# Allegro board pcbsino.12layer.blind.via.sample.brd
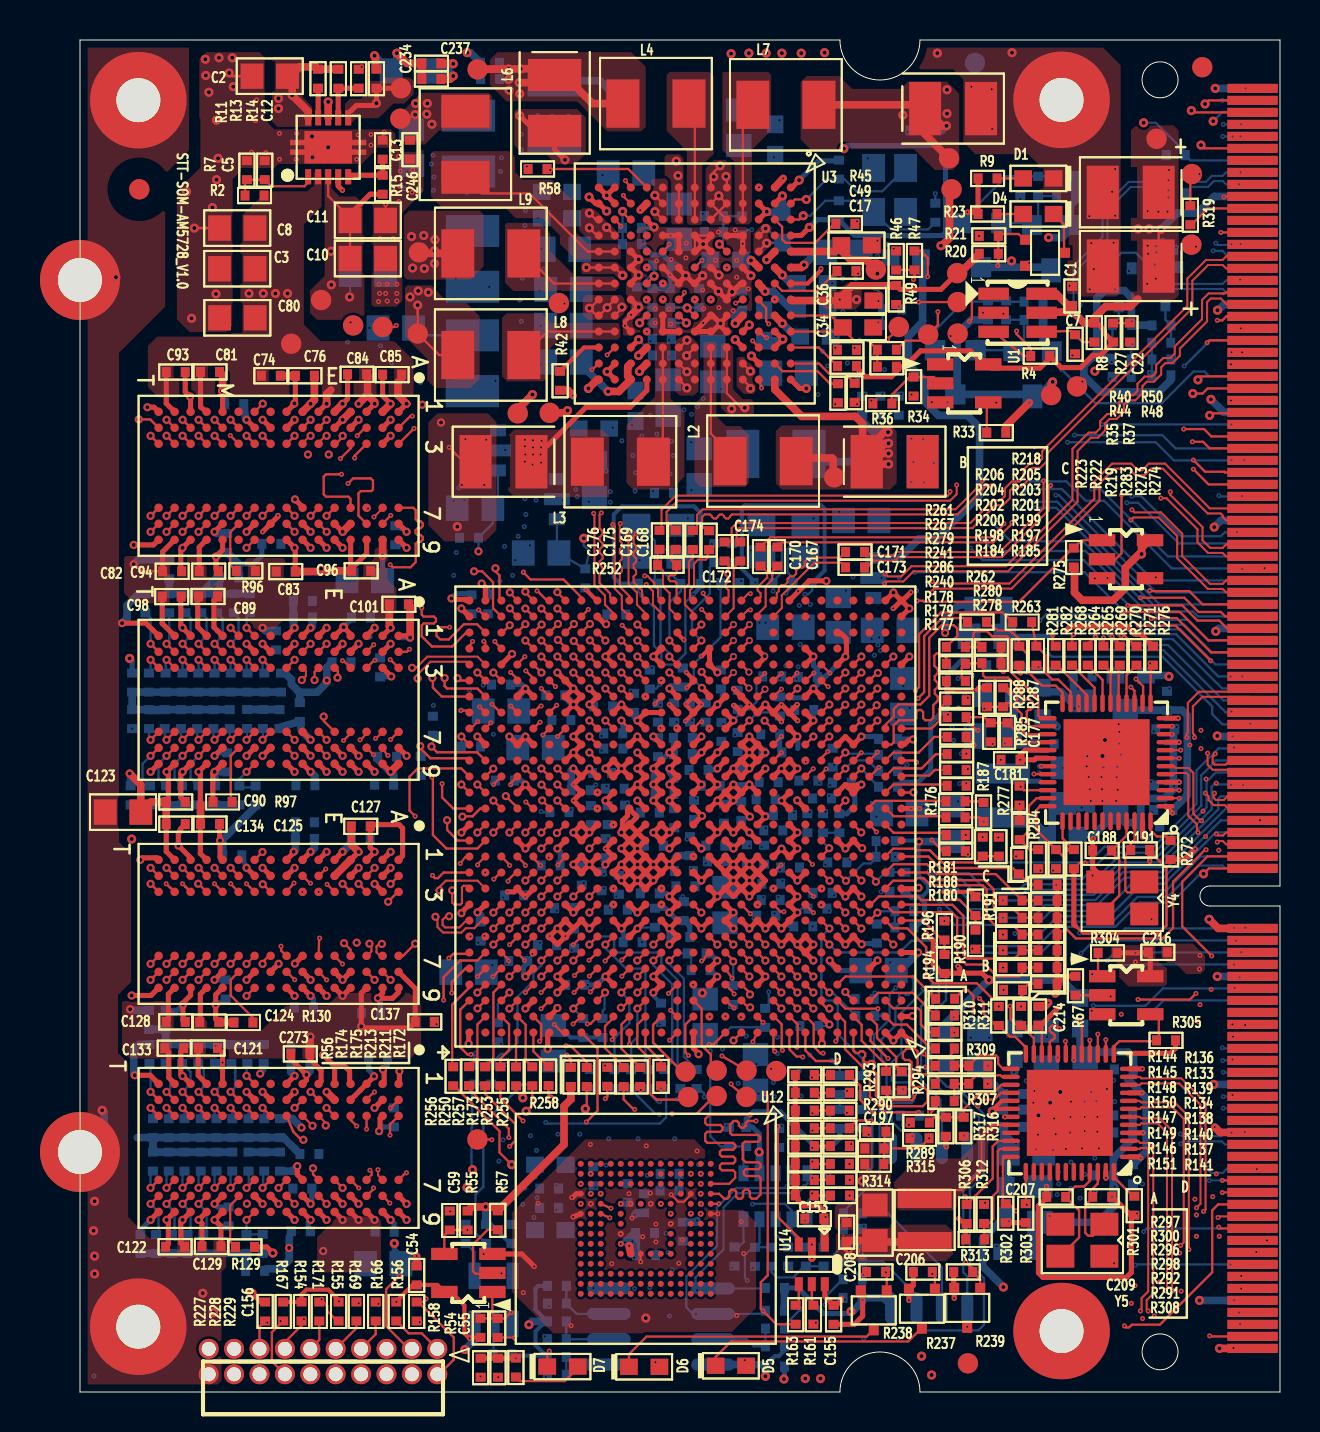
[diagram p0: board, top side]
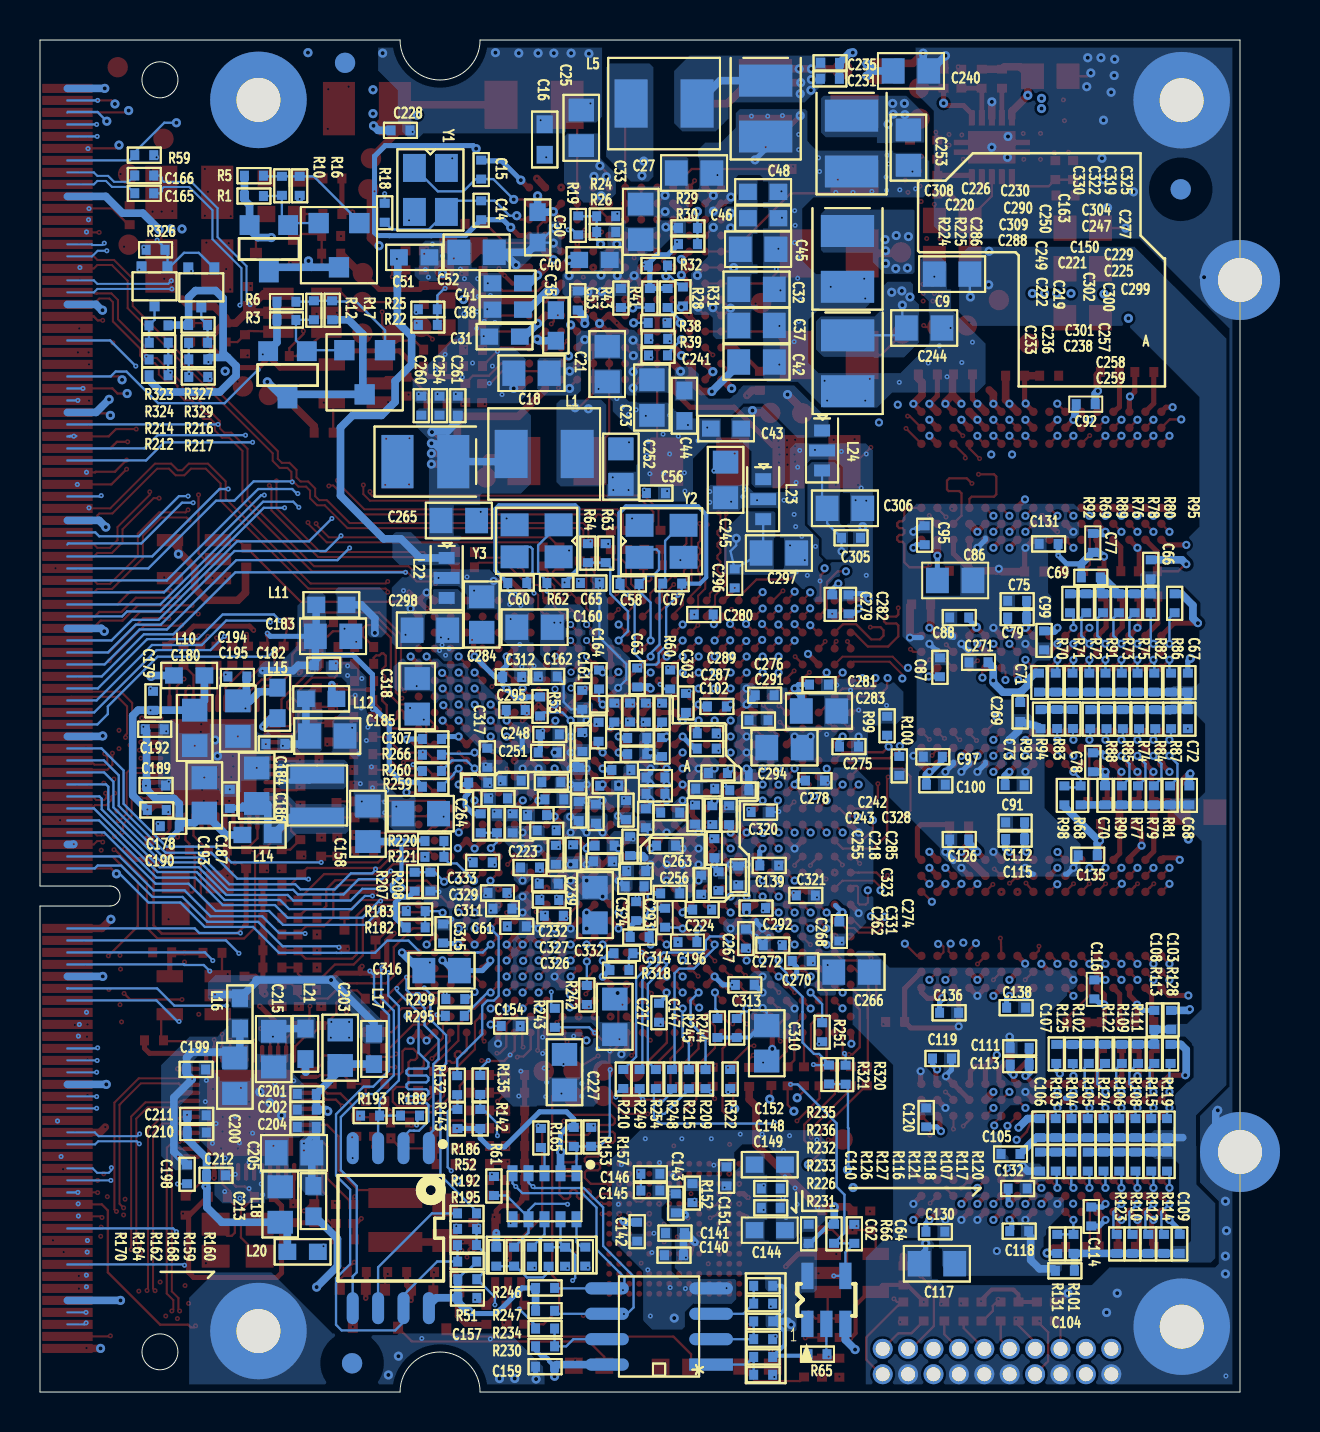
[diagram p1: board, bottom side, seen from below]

Outline 60 x 67.6 mm; copper layers: TOP, GND_L2, INT_L3, GND_L4, SIG_L5, PWR_L6, PWR_L7, SIG_L8, GND_L9, SIG_L10, GND_L11, BOTTOM. Coordinates in mm from the lower left corner of the outline.
Outline path: circle c54,2.01 r0.9 ; circle c54,65.61 r0.9 ; 0,67.6 38,67.6 arc(40,65.6) 42,67.6 60,67.6 60,25.3 56.5,25.3 arc(56,24.8) 56.5,24.3 60,24.3 60,0 42,0 arc(40,2) 38,0 0,0 0,67.6

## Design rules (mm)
net group DDR1_CLK: nets DDR1_CLK_N DDR1_CLK_P
net group EMMC_NAND_MMC2_DAT2: nets EMMC_NAND__MMC2_DAT2 EMMC_NAND_MMC2_DAT2
net group LDO_VRTC: nets N25853972 N32694377
net group R_QSPI_FLASH_QSPI1_SCLK: nets R__QSPI_FLASH_QSPI1_SCLK R_QSPI_FLASH_QSPI1_SCLK
net group RTC_CLKOUT_1V8: nets N29245750 RTC_CLKOUT_1V8
net group SATA1_RX0: nets SATA1_RX0_N SATA1_RX0_P
net group SATA1_TX0_N: nets SATA1_TX0_N SODIMM_SATA1_TX0_N
net group SATA1_TX0_P: nets SATA1_TX0_P SODIMM_SATA1_TX0_P
net group SODIMM_ETH0_MDI0: nets SODIMM_ETH0_MDI0_N SODIMM_ETH0_MDI0_P
net group SODIMM_ETH0_MDI2: nets SODIMM_ETH0_MDI2_N SODIMM_ETH0_MDI2_P
net group SODIMM_ETH0_MDI3: nets SODIMM_ETH0_MDI3_N SODIMM_ETH0_MDI3_P
net group SODIMM_ETH1_MDI0: nets SODIMM_ETH1_MDI0_N SODIMM_ETH1_MDI0_P
net group SODIMM_ETH1_MDI1: nets SODIMM_ETH1_MDI1_N SODIMM_ETH1_MDI1_P
net group SODIMM_ETH1_MDI3: nets SODIMM_ETH1_MDI3_N SODIMM_ETH1_MDI3_P
net group SODIMM_SATA1_RX0: nets SODIMM_SATA1_RX0_N SODIMM_SATA1_RX0_P
net group SODIMM_UART8_RXD: nets SODIMM__UART8_RXD SODIMM_UART8_RXD
net group SODIMM_USB1_D: nets SODIMM_USB1_D_N SODIMM_USB1_D_P
net group SODIMM_USB1_RX0: nets SODIMM_USB1_RX0_N SODIMM_USB1_RX0_P
net group SODIMM_USB1_TX0: nets SODIMM_USB1_TX0_N SODIMM_USB1_TX0_P
net group SODIMM_USB2_D: nets SODIMM_USB2_D_N SODIMM_USB2_D_P
net group USB1_TX0: nets USB1_TX0_N USB1_TX0_P
net group D1: nets DDR2_D15
net group EMAC[0]_RXC/PHYAD1: nets EMAC[0]_RXC/PHYAD1
net group EMAC[0]_RXCTL/PHYAD2: nets EMAC[0]_RXCTL/PHYAD2
net group EMAC[0]_RXD2/CFG_MODE1: nets R_EMAC[0]_RXD2
net group EMAC[0]_RXD3/CFG_MODE2: nets R_EMAC[0]_RXD3
net group EMAC[0]_TXC: nets EMAC[0]_TXC
net group EMAC[0]_TXCTL: nets EMAC[0]_TXCTL
net group EMAC[0]_TXD0: nets EMAC[0]_TXD0
net group EMAC[0]_TXD1: nets EMAC[0]_TXD1
net group EMAC[0]_TXD2: nets EMAC[0]_TXD2
net group EMAC[0]_TXD3: nets EMAC[0]_TXD3
net group EMAC[1]_RXCTL/PHYAD2: nets R_EMAC[1]_RXCTL
net group EMAC[1]_RXD1/CFG_MODE0: nets R_EMAC[1]_RXD1
net group EMAC[1]_TXC: nets EMAC[1]_TXC
net group EMAC[1]_TXCTL: nets EMAC[1]_TXCTL
net group EMAC[1]_TXD0: nets EMAC[1]_TXD0
net group EMAC[1]_TXD1: nets EMAC[1]_TXD1
net group EMAC[1]_TXD2: nets EMAC[1]_TXD2
net group EMAC[1]_TXD3: nets EMAC[1]_TXD3
net group HDMI: nets SODIMM_HDMI1_CLOCK_N SODIMM_HDMI1_CLOCK_P SODIMM_HDMI1_DATA0_N SODIMM_HDMI1_DATA0_P SODIMM_HDMI1_DATA1_N SODIMM_HDMI1_DATA1_P SODIMM_HDMI1_DATA2_N SODIMM_HDMI1_DATA2_P
net group LJCB_CLK_N: nets SODIMM_PCIE_REF_LJCB_CLK_N
net group LJCB_CLK_P: nets SODIMM_PCIE_REF_LJCB_CLK_P
net group PCIE_TX0_N: nets SODIMM_PCIE_TX0_N
net group PCIE_TX0_P: nets SODIMM_PCIE_TX0_P
net group PCIE_TX1_N: nets SODIMM_PCIE_TX1_N
net group PCIE_TX1_P: nets SODIMM_PCIE_TX1_P
net group RSTOUTN: nets R_QSPI_FLASH_QSPI1_D3
nets with their own width: min track width 0.102; nets GND
nets with their own width: min track width 0.254; nets LDO_VRTC

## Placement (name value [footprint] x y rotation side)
C1  0.1uF  [0402]  49.6 54.8 270 top
C2  10uF  [0805]  9.49 65.79 180 top
C3  10uF  [0805]  7.86 56.16 0 top
C4  47uF  [1210]  52.53 56.3 180 top
C5  .001uF  [0402]  9.23 61.09 90 top
C6  47uF  [1210]  52.53 59.98 180 top
C7  DNI  [0402]  49.75 52.39 270 top
C8  10uF  [0805]  7.86 58.2 0 top
C9  10uF  [0805]  14.39 55.89 0 bottom
C10  10uF  [0805]  14.39 56.67 0 top
C11  10uF  [0805]  14.39 58.58 0 top
C12  0.1uF  [0402]  14.82 65.66 90 top
C13  DNI  [0402]  15.13 62.12 90 top
C14  10pF  [0402]  37.94 59.09 270 bottom
C15  10pF  [0402]  37.94 61.12 90 bottom
C16  2.2uF  [0603]  34.76 62.62 90 bottom
C17  0.1uF  [0402]  38.32 56.05 180 top
C18  4.7uF  [0805]  35.42 50.94 0 bottom
C19  47uF  [1210]  40.73 46.52 0 top
C20  47uF  [1210]  40.73 46.52 0 bottom
C21  4.7uF  [0805]  31.64 51.4 270 bottom
C22  0.1uF  [0402]  52.49 52.97 270 top
C23  4.7uF  [0805]  29.4 49.72 270 bottom
C24  47uF  [1210]  21.18 46.51 180 top
C25  4.7uF  [0805]  32.94 63.21 90 bottom
C26  47uF  [1210]  23.73 64.46 270 top
C27  4.7uF  [0805]  27.3 60.95 180 bottom
C28  47uF  [1210]  23.71 64.17 270 bottom
C29  47uF  [1210]  19.42 62.42 270 bottom
C30  47uF  [1210]  43.65 64.17 0 top
C31  2.2uF  [0603]  36.77 52.77 180 bottom
C32  4.7uF  [0805]  24.17 55.13 180 bottom
C33  4.7uF  [0805]  29.96 58.51 270 bottom
C34  2.2uF  [0603]  38.9 53.23 0 top
C35  2.2uF  [0603]  34.21 53.33 90 bottom
C36  2.2uF  [0603]  38.9 54.57 180 top
C37  4.7uF  [0805]  24.17 53.33 180 bottom
C38  2.2uF  [0603]  36.62 54.12 0 bottom
C39  47uF  [1210]  19.62 51.44 270 bottom
C40  2.2uF  [0603]  32.28 56.6 0 bottom
C41  2.2uF  [0603]  36.62 55.44 180 bottom
C42  10uF  [0805]  24.17 51.5 180 bottom
C43  2.2uF  [0603]  25.7 48.17 180 bottom
C44  2.2uF  [0603]  27.78 49.31 90 bottom
C45  4.7uF  [0805]  24.1 57.14 180 bottom
C46  2.2uF  [0603]  23.84 58.69 0 bottom
C47  47uF  [1210]  19.62 56.66 270 bottom
C48  2.2uF  [0603]  23.84 60.01 0 bottom
C49  2.2uF  [0603]  38.83 57.34 180 top
C50  2.2uF  [0603]  35.12 58.23 270 bottom
C51  2.2uF  [0603]  41.29 56.73 0 bottom
C52  10uF  [0805]  38.17 56.99 0 bottom
C53  0.1uF  [0402]  33.11 54.57 90 bottom
C54  0.1uF  [0402]  16.83 5.83 90 top
C55  0.1uF  [0402]  20.88 3.2 270 top
C56  0.1uF  [0402]  29.2 44.95 180 bottom
C57  18pF  [0402]  28.39 40.42 180 bottom
C58  18pF  [0402]  30.52 40.4 0 bottom
C59  DNI  [0402]  18.49 8.58 90 top
C60  DNI  [0402]  36.14 40.45 0 bottom
C61  0.1uF  [0402]  36.16 23.28 0 bottom
C62  0.1uF  [0402]  21.57 7.91 90 bottom
C63  0.1uF  [0402]  30.14 35.73 90 bottom
C64  DNI  [0402]  19.28 7.91 90 bottom
C65  0.1uF  [0402]  32.5 40.45 0 bottom
C66  0.1uF  [0402]  4.46 41.14 90 bottom
C67  0.1uF  [0402]  2.61 35.47 90 bottom
C68  0.1uF  [0402]  2.53 29.83 90 bottom
C69  0.1uF  [0402]  7.46 40.73 0 bottom
C70  0.1uF  [0402]  6.75 29.83 90 bottom
C71  0.1uF  [0402]  10.05 35.47 90 bottom
C72  0.1uF  [0402]  2.61 33.64 270 bottom
C73  0.1uF  [0402]  9.97 33.64 270 bottom
C74  0.1uF  [0402]  9.54 50.81 0 top
C75  0.1uF  [0402]  11.14 39.56 180 bottom
C76  0.1uF  [0402]  11.24 50.81 0 top
C77  0.1uF  [0402]  7.36 42.46 270 bottom
C78  0.1uF  [0402]  7.36 31.48 270 bottom
C79  0.1uF  [0402]  11.14 38.72 0 bottom
C80  10uF  [0805]  7.87 53.71 180 top
C81  0.1uF  [0402]  6.5 51 180 top
C82  0.1uF  [0402]  4.61 41.03 180 top
C83  0.1uF  [0402]  10.29 41.02 0 top
C84  0.1uF  [0402]  13.85 50.88 0 top
C85  0.1uF  [0402]  15.61 50.87 0 top
C86  10uF  [0805]  14.24 40.58 0 bottom
C87  0.1uF  [0402]  15 36.23 90 bottom
C88  0.1uF  [0402]  14.04 38.72 0 bottom
C89  0.1uF  [0402]  6.4 39.78 180 top
C90  0.1uF  [0402]  4.79 29.5 180 top
C91  0.1uF  [0402]  11.27 30.34 180 bottom
C92  0.1uF  [0402]  7.71 49.39 180 bottom
C93  0.1uF  [0402]  4.79 51 0 top
C94  0.1uF  [0402]  6.44 41.04 0 top
C95  0.1uF  [0402]  15.77 42.84 270 bottom
C96  0.1uF  [0402]  14.06 41.06 0 top
C97  0.1uF  [0402]  15.36 31.76 180 bottom
C98  0.1uF  [0402]  4.58 39.77 0 top
C99  0.1uF  [0402]  9.8 37.58 90 bottom
C100  0.1uF  [0402]  15.21 30.37 0 bottom
C101  0.1uF  [0402]  15.94 39.38 180 top
C102  0.1uF  [0402]  26.66 32.93 180 bottom
C103  0.1uF  [0402]  3.45 18.61 90 bottom
C104  0.1uF  [0402]  8.75 6.06 0 bottom
C105  0.1uF  [0402]  11.47 11.9 0 bottom
C106  0.1uF  [0402]  10 13.2 90 bottom
C107  0.1uF  [0402]  9.19 16.9 270 bottom
C108  0.1uF  [0402]  4.28 18.61 90 bottom
C109  0.1uF  [0402]  3.01 7.4 90 bottom
C110  0.1uF  [0402]  10 11.52 270 bottom
C111  0.1uF  [0402]  11.02 17.21 180 bottom
C112  0.1uF  [0402]  11.24 28.49 180 bottom
C113  0.1uF  [0402]  11.02 16.37 0 bottom
C114  0.1uF  [0402]  7.43 8.78 270 bottom
C115  0.1uF  [0402]  11.24 27.65 0 bottom
C116  0.1uF  [0402]  7.28 20.13 270 bottom
C117  10uF  [0805]  15.16 6.41 0 bottom
C118  0.1uF  [0402]  11.04 8.04 180 bottom
C119  0.1uF  [0402]  14.9 16.68 180 bottom
C120  0.1uF  [0402]  15.69 13.73 90 bottom
C121  0.1uF  [0402]  6.4 17.2 180 top
C122  0.1uF  [0402]  4.75 7.26 180 top
C123  10uF  [0805]  2.15 28.99 180 top
C124  0.1uF  [0402]  6.46 18.49 180 top
C125  0.1uF  [0402]  6.5 28.4 180 top
C126  0.1uF  [0402]  14.04 27.62 0 bottom
C127  0.1uF  [0402]  14.04 28.28 0 top
C128  0.1uF  [0402]  4.79 18.5 180 top
C129  0.1uF  [0402]  6.57 7.28 0 top
C130  0.1uF  [0402]  15.23 8.01 0 bottom
C131  0.1uF  [0402]  9.57 42.41 180 bottom
C132  0.1uF  [0402]  11.12 10.17 0 bottom
C133  0.1uF  [0402]  4.71 17.19 0 top
C134  0.1uF  [0402]  4.79 28.39 0 top
C135  0.1uF  [0402]  7.61 26.84 180 bottom
C136  0.1uF  [0402]  14.55 18.96 0 bottom
C137  0.1uF  [0402]  17.24 18.5 0 top
C138  0.1uF  [0402]  11.19 19.22 0 bottom
C139  0.1uF  [0402]  23.54 26.33 0 bottom
C140  0.1uF  [0402]  28.3 6.84 180 bottom
C141  0.1uF  [0402]  28.25 7.94 180 bottom
C142  0.1uF  [0402]  30.14 8.01 90 bottom
C143  0.1uF  [0402]  28.21 9.44 270 bottom
C144  2.2uF  [0603]  23.51 8.09 180 bottom
C145  0.1uF  [0402]  29.48 10.07 180 bottom
C146  1uF  [0402]  29.48 10.91 0 bottom
C147  0.1uF  [0402]  29.05 18.96 90 bottom
C148  0.1uF  [0402]  23.46 10.17 0 bottom
C149  0.1uF  [0402]  23.46 9.21 0 bottom
C150  0.1uF  [0402]  30.93 31.1 0 bottom
C151  0.1uF  [0402]  25.67 10.78 270 bottom
C152  2.2uF  [0603]  23.51 11.37 180 bottom
C153  0.1uF  [0402]  36.72 8.67 180 top
C154  0.1uF  [0402]  36.47 18.3 180 bottom
C155  0.1uF  [0402]  37.68 3.86 270 top
C156  0.1uF  [0402]  9.26 4.03 90 top
C157  0.1uF  [0402]  38.63 4.7 0 bottom
C158  10uF  [0805]  43.6 28.41 90 bottom
C159  0.1uF  [0402]  34.75 1.27 0 bottom
C160  10uF  [0805]  35.27 38.24 0 bottom
C161  0.1uF  [0402]  32.88 34.61 90 bottom
C162  0.1uF  [0402]  34.61 35.78 0 bottom
C163  0.1uF  [0402]  32.07 33.01 90 bottom
C164  0.1uF  [0402]  32.05 35.62 90 bottom
C165  0.1uF  [0402]  54.79 59.94 0 bottom
C166  0.1uF  [0402]  54.79 60.82 0 bottom
C167  0.1uF  [0402]  34.87 41.77 270 top
C168  0.1uF  [0402]  31.46 42.59 90 top
C169  0.1uF  [0402]  30.64 42.6 90 top
C170  0.1uF  [0402]  34.03 41.77 270 top
C171  0.1uF  [0402]  38.75 42 180 top
C172  0.1uF  [0402]  32.22 42.02 90 top
C173  0.1uF  [0402]  38.75 41.24 180 top
C174  0.1uF  [0402]  33.01 42.02 90 top
C175  0.1uF  [0402]  29.79 42.61 270 top
C176  0.1uF  [0402]  28.97 42.61 270 top
C177  DNI  [0402]  46.37 32.98 270 top
C178  0.1uF  [0402]  54.16 29.1 0 bottom
C179  0.1uF  [0402]  54.35 34.56 270 bottom
C180  10uF  [0805]  52.27 33.2 270 bottom
C181  0.1uF  [0402]  46.52 31.61 180 top
C182  0.1uF  [0402]  45.81 36.34 180 bottom
C183  10uF  [0805]  45.35 37.78 180 bottom
C184  0.1uF  [0402]  48.23 32.4 0 bottom
C185  10uF  [0805]  45.64 32.8 180 bottom
C186  10uF  [0805]  49.17 30.32 90 bottom
C187  0.1uF  [0402]  50.51 29.65 90 bottom
C188  27pF  [0402]  51.11 27.08 180 top
C189  0.1uF  [0402]  54.2 30.33 180 bottom
C190  0.1uF  [0402]  53.51 28.28 0 bottom
C191  27pF  [0402]  53.01 27.1 0 top
C192  0.1uF  [0402]  54.26 33.14 180 bottom
C193  10uF  [0805]  51.78 29.83 90 bottom
C194  0.1uF  [0402]  50.13 35.78 0 bottom
C195  10uF  [0805]  50.11 33.67 270 bottom
C196  0.1uF  [0402]  27.63 22.49 0 bottom
C197  DNI  [0402]  39.72 12.18 180 top
C198  0.1uF  [0402]  52.65 10.88 270 bottom
C199  0.1uF  [0402]  52.19 16.13 180 bottom
C200  10uF  [0805]  50.26 15.81 270 bottom
C201  0.1uF  [0402]  46.66 14.9 0 bottom
C202  0.1uF  [0402]  46.66 14.12 0 bottom
C203  10uF  [0805]  44.99 17.22 90 bottom
C204  0.1uF  [0402]  46.66 13.25 0 bottom
C205  10uF  [0805]  47.3 11.96 0 bottom
C206  10uF  [0805]  39.75 8.47 90 top
C207  27pF  [0402]  48.81 9.75 180 top
C208  0.1uF  [0402]  38.33 8 90 top
C209  27pF  [0402]  51.11 9.76 0 top
C210  0.1uF  [0402]  52.16 12.98 180 bottom
C211  0.1uF  [0402]  52.16 13.83 180 bottom
C212  0.1uF  [0402]  51.2 10.83 180 bottom
C213  10uF  [0805]  47.99 9.38 90 bottom
C214  0.1uF  [0402]  47.92 18.8 90 top
C215  10uF  [0805]  48.31 17.15 270 bottom
C216  0.1uF  [0402]  53.89 21.98 0 top
C217  10uF  [0805]  31.26 18.76 270 bottom
C218  0.1uF  [0402]  26.38 28.84 270 bottom
C219  0.1uF  [0402]  32.2 28.92 90 bottom
C220  0.1uF  [0402]  37.1 29.68 0 bottom
C221  0.1uF  [0402]  31.54 30.32 180 bottom
C222  0.1uF  [0402]  33.06 29.05 90 bottom
C223  0.1uF  [0402]  35.5 26.23 180 bottom
C224  0.1uF  [0402]  26.89 24.12 180 bottom
C225  0.1uF  [0402]  29.23 29.91 0 bottom
C226  0.1uF  [0402]  36.42 30.57 0 bottom
C227  10uF  [0805]  33.77 15.99 270 bottom
C228  0.1uF  [0402]  41.98 63.08 180 bottom
C229  0.1uF  [0402]  29.23 30.72 0 bottom
C230  0.1uF  [0402]  34.43 30.49 180 bottom
C231  0.1uF  [0402]  20.51 65.66 180 bottom
C232  0.1uF  [0402]  34.56 25.41 0 bottom
C233  0.1uF  [0402]  34.21 26.86 90 bottom
C234  0.1uF  [0402]  17.57 65.65 180 top
C235  0.1uF  [0402]  20.5 66.46 180 bottom
C236  0.1uF  [0402]  33.34 26.89 90 bottom
C237  0.1uF  [0402]  17.57 66.43 180 top
C238  0.1uF  [0402]  31.84 26.53 180 bottom
C239  10uF  [0805]  32.25 24.35 270 bottom
C240  10uF  [0805]  16.45 66.05 180 bottom
C241  0.1uF  [0402]  29.1 51.83 0 bottom
C242  0.1uF  [0402]  26.1 30.95 180 bottom
C243  0.1uF  [0402]  26.74 30.16 180 bottom
C244  10uF  [0805]  15.79 53.2 180 bottom
C245  10uF  [0805]  25.72 45.61 270 bottom
C246  0.1uF  [0402]  16.5 62.12 270 top
C247  0.1uF  [0402]  30.14 31.89 180 bottom
C248  0.1uF  [0402]  34.51 32.88 0 bottom
C249  0.1uF  [0402]  33.06 30.75 270 bottom
C250  0.1uF  [0402]  32.88 32.5 90 bottom
C251  0.1uF  [0402]  34.62 31.98 0 bottom
C252  10uF  [0805]  30.95 46.27 270 bottom
C253  10uF  [0805]  16.58 62.22 270 bottom
C254  0.1uF  [0402]  40.02 49.31 90 bottom
C255  0.1uF  [0402]  27.25 28.87 90 bottom
C256  0.1uF  [0402]  28.49 24.93 0 bottom
C257  0.1uF  [0402]  30.5 27.29 90 bottom
C258  0.1uF  [0402]  30.19 26.05 0 bottom
C259  0.1uF  [0402]  30.27 25.29 0 bottom
C260  0.1uF  [0402]  40.94 49.31 90 bottom
C261  0.1uF  [0402]  39.11 49.31 90 bottom
C262  0.1uF  [0402]  26.94 25.36 270 bottom
C263  0.1uF  [0402]  28.69 27.32 0 bottom
C264  10uF  [0805]  40.96 28.92 0 bottom
C265  10uF  [0805]  39.06 43.57 180 bottom
C266  10uF  [0805]  19.42 20.99 0 bottom
C267  0.1uF  [0402]  24.71 22.67 270 bottom
C268  0.1uF  [0402]  20.03 23.03 270 bottom
C269  0.1uF  [0402]  10.99 34 90 bottom
C270  0.1uF  [0402]  21.91 21.55 180 bottom
C271  0.1uF  [0402]  13.07 36.49 180 bottom
C272  0.1uF  [0402]  23.36 22.34 180 bottom
C273  0.1uF  [0402]  11.02 16.9 180 top
C274  0.1uF  [0402]  25.09 25.82 270 bottom
C275  0.1uF  [0402]  19.55 32.27 180 bottom
C276  0.1uF  [0402]  23.77 34.84 180 bottom
C277  0.1uF  [0402]  28.9 32.25 270 bottom
C278  0.1uF  [0402]  21.25 30.57 180 bottom
C279  0.1uF  [0402]  20.39 39.38 270 bottom
C280  0.1uF  [0402]  26.81 38.88 0 bottom
C281  0.1uF  [0402]  21.05 35.37 180 bottom
C282  0.1uF  [0402]  19.58 39.38 90 bottom
C283  10uF  [0805]  21.05 34.05 180 bottom
C284  10uF  [0805]  37.91 38.88 90 bottom
C285  0.1uF  [0402]  25.54 28.84 90 bottom
C286  0.1uF  [0402]  36.36 28.44 90 bottom
C287  0.1uF  [0402]  26.66 32.17 180 bottom
C288  0.1uF  [0402]  34.66 28.08 180 bottom
C289  0.1uF  [0402]  26.15 34.28 180 bottom
C290  0.1uF  [0402]  34.28 29.63 180 bottom
C291  0.1uF  [0402]  24.07 33.59 180 bottom
C292  0.1uF  [0402]  24.2 24.19 180 bottom
C293  0.1uF  [0402]  28.74 23.71 90 bottom
C294  10uF  [0805]  22.78 32.22 180 bottom
C295  0.1uF  [0402]  36.21 34.1 180 bottom
C296  0.1uF  [0402]  25.26 40.68 270 bottom
C297  10uF  [0805]  23.05 41.95 180 bottom
C298  10uF  [0805]  40.5 38.09 0 bottom
C299  0.1uF  [0402]  28.49 28.97 0 bottom
C300  0.1uF  [0402]  29.71 28.69 90 bottom
C301  0.1uF  [0402]  31.77 27.32 180 bottom
C302  0.1uF  [0402]  30.7 29.1 90 bottom
C303  0.1uF  [0402]  27.7 34.46 90 bottom
C304  0.1uF  [0402]  30.14 32.7 180 bottom
C305  0.1uF  [0402]  19.45 42.71 180 bottom
C306  10uF  [0805]  19.75 44.18 180 bottom
C307  0.1uF  [0402]  40.4 32.65 0 bottom
C308  0.1uF  [0402]  38.09 30.47 180 bottom
C309  0.1uF  [0402]  35.15 28.84 0 bottom
C310  10uF  [0805]  23.66 17.44 270 bottom
C311  0.1uF  [0402]  36.87 24.17 0 bottom
C312  0.1uF  [0402]  36.39 35.75 180 bottom
C313  0.1uF  [0402]  24.76 20.36 0 bottom
C314  0.1uF  [0402]  30.01 22.75 0 bottom
C315  0.1uF  [0402]  39.84 22.92 90 bottom
C316  10uF  [0805]  39.92 21.07 0 bottom
C317  0.1uF  [0402]  37.63 31.71 270 bottom
C318  10uF  [0805]  41.14 34.79 270 bottom
C319  1uF  [0402]  29.71 33.97 270 bottom
C320  1uF  [0402]  23.97 28.99 180 bottom
C321  1uF  [0402]  21.71 24.83 0 bottom
C322  1uF  [0402]  30.5 33.97 90 bottom
C323  1uF  [0402]  26.28 27.19 90 bottom
C324  1uF  [0402]  30.19 24.04 270 bottom
C325  1uF  [0402]  28.9 33.97 270 bottom
C326  1uF  [0402]  34.31 23.81 180 bottom
C327  1uF  [0402]  34.54 24.6 180 bottom
C328  1uF  [0402]  25.04 30.09 180 bottom
C329  1uF  [0402]  37.13 24.96 180 bottom
C330  1uF  [0402]  31.28 33.97 90 bottom
C331  1uF  [0402]  26.08 25.54 270 bottom
C332  1uF  [0402]  30.83 21.93 0 bottom
C333  1uF  [0402]  37.86 26.48 180 bottom
D1  LTST-C191KGKT  [LED_0603]  47.92 60.68 180 top
D2  TLVH431LIL3T  [SOT23-3L]  45.05 57.34 0 bottom
D3  TLVH431LIL3T  [SOT23-3L]  43.77 50.99 0 bottom
D4  LTST-C191KGKT  [LED_0603]  47.92 58.9 180 top
D5  LTST-C191KGKT  [LED_0603]  32.55 1.31 0 top
D6  LTST-C191KRKT  [LED_0603]  28.21 1.26 0 top
D7  LTST-C191TBKT  [LED_0603]  24.12 1.27 0 top
L1  1.0uH  [IND_IHLP1616AB]  34.79 46.9 0 bottom
L2  1.0uH  [IND_IHLP1616AB]  34.15 46.55 0 top
L3  1.0uH  [IND_IHLP1616AB]  27.02 46.51 180 top
L4  1.0uH  [IND_IHLP1616AB]  28.8 64.42 180 top
L5  1.0uH  [IND_IHLP1616AB]  28.8 64.42 180 bottom
L6  1.0uH  [IND_IHLP1616AB]  19.27 62.39 90 top
L7  1.0uH  [IND_IHLP1616AB]  35.29 64.36 0 top
L8  1.0uH  [IND_IHLP1616AB]  20.54 51.85 180 top
L9  1.0uH  [IND_IHLP1616AB]  20.54 56.93 180 top
L10  BLM18KG601SN1D  [0603]  52.54 35.83 0 bottom
L11  BLM18KG601SN1D  [0603]  45.43 39.36 180 bottom
L12  BLM18KG601SN1D  [0603]  45.94 34.66 180 bottom
L13  2.2uH_1A  [SRN3015]  46.14 29.83 180 bottom
L14  BLM18KG601SN1D  [0603]  49.12 27.85 180 bottom
L15  BLM18KG601SN1D  [0603]  48.12 34.46 270 bottom
L16  BLM18KG601SN1D  [0603]  50 18.94 90 bottom
L17  BLM18KG601SN1D  [0603]  43.3 17.16 90 bottom
L18  BLM18KG601SN1D  [0603]  46.33 9.54 270 bottom
L19  2.2uH_1A  [SRN3015]  42.23 8.6 0 top
L20  BLM18KG601SN1D  [0603]  46.87 7.01 180 bottom
L21  BLM18KG601SN1D  [0603]  46.72 17.41 270 bottom
L22  NFM21PC474R1C3D  [FILT-NFM21PC]  39.67 40.7 270 bottom
L23  NFM21PC474R1C3D  [FILT-NFM21PC]  23.84 44.64 270 bottom
L24  NFM21PC474R1C3D  [FILT-NFM21PC]  20.9 47.08 270 bottom
MH1  MOUNT_HOLE  [2P2_5P0_MM_PL]  49.08 64.6 0 top
MH2  MOUNT_HOLE  [2P2_5P0_MM_PL]  49.08 3.05 0 top
MH3  MOUNT_HOLE  [2P2_5P0_MM_PL]  2.91 3.27 0 top
MH4  MOUNT_HOLE  [2P2_5P0_MM_PL]  2.92 64.59 0 top
MH5  MOUNT_HOLE  [2P0_4P0_MM_PL]  0 55.6 0 top
MH6  MOUNT_HOLE  [2P0_4P0_MM_PL]  0 12 0 top
NOREF  -  [unnamed]  56.11 66.24 0 top
NOREF#2  -  [#2]  36.54 -92.04 0 top
NOREF#3  -  [unnamed]  2.96 60.13 0 top
NOREF#4  -  [#2]  -387 -278.1 0 top
NOREF#5  -  [unnamed]  44.4 1.43 0 top
NOREF#6  -  [#2]  -386.87 -278.02 0 top
NOREF#7  -  [unnamed]  2.96 60.13 180 bottom
NOREF#8  -  [unnamed]  44.4 1.44 180 bottom
NOREF#9  -  [unnamed]  44.75 66.46 180 bottom
P1  DNI  [PLLD1_27-20R]  12.15 1.52 180 top
Q1  MMBT2907A-7-F  [SOT23]  48.56 57.16 0 bottom
Q2  MMBT2907A-7-F  [SOT23]  47.63 50.86 0 bottom
Q3  BSS138W-7-F  [SOT323]  48.25 56.96 270 top
Q4  BSS138W-7-F  [SOT323]  42.1 4.16 180 top
Q5  BSS138W-7-F  [SOT323]  39.69 4.08 180 top
Q6  BSS138W-7-F  [SOT323]  44.36 4.21 180 top
Q7  BSS138W-7-F  [SOT323]  54.27 55.28 0 bottom
Q8  BSS138W-7-F  [SOT323]  51.93 55.23 0 bottom
R1  499  [0402]  49.3 59.8 0 bottom
R2  10K,1%  [0402]  8.73 59.82 180 top
R3  499  [0402]  47.68 53.6 0 bottom
R4  10K  [0402]  48.01 51.8 0 top
R5  DNI  [0402]  49.3 60.82 0 bottom
R6  DNI  [0402]  47.68 54.52 0 bottom
R7  10K,1%  [0402]  8.34 61.09 270 top
R8  47K  [0402]  50.72 52.97 90 top
R9  1K  [0402]  45.38 60.68 0 top
R10  10K  [0402]  47.91 60.31 90 bottom
R11  100K  [0402]  11.9 65.66 270 top
R12  10K  [0402]  46.31 54.09 90 bottom
R13  10K  [0402]  12.92 65.66 90 top
R14  DNI  [0402]  13.93 65.66 90 top
R15  0  [0402]  15.13 60.36 90 top
R16  24.3K  [0402]  47.02 60.31 90 bottom
R17  24.3K  [0402]  45.39 54.09 90 bottom
R18  DNI  [0402]  42.77 58.96 270 bottom
R19  DNI  [0402]  33.09 58.33 90 bottom
R20  10K  [0402]  45.44 56.91 180 top
R21  DNI  [0402]  45.44 57.8 180 top
R22  2K  [0402]  40.61 53.35 180 bottom
R23  1K  [0402]  45.38 58.9 0 top
R24  10K  [0402]  31.69 58.79 0 bottom
R25  1.74K  [0402]  40.61 54.13 180 bottom
R26  DNI  [0402]  31.69 58 0 bottom
R27  10K  [0402]  51.66 52.97 90 top
R28  10K  [0402]  28.62 54.7 270 bottom
R29  10K  [0402]  27.6 58.2 0 bottom
R30  DNI  [0402]  27.6 57.39 0 bottom
R31  DNI  [0402]  27.86 54.78 270 bottom
R32  10K  [0402]  29.1 56.32 0 bottom
R33  10K  [0402]  45.81 47.97 180 top
R34  10K  [0402]  41.68 50.27 270 top
R35  10K  [0402]  37.9 49.94 90 top
R36  0  [0402]  40.12 49.43 180 top
R37  DNI  [0402]  38.73 49.96 90 top
R38  10K  [0402]  29.12 53.46 0 bottom
R39  DNI  [0402]  29.09 52.66 180 bottom
R40  10K  [0402]  38.35 52.11 180 top
R41  10K  [0402]  29.51 54.7 270 bottom
R42  10K  [0402]  24 50.56 90 top
R43  DNI  [0402]  30.95 54.7 90 bottom
R44  0  [0402]  38.35 51.3 180 top
R45  0  [0402]  38.27 58.41 180 top
R46  DNI  [0402]  40.81 56.58 90 top
R47  1K  [0402]  41.72 56.58 90 top
R48  0  [0402]  40.34 51.27 0 top
R49  3.9K  [0402]  40.81 54.85 270 top
R50  DNI  [0402]  40.34 52.12 180 top
R51  DNI  [0402]  38.64 5.64 0 bottom
R52  DNI  [0402]  38.65 8.16 0 bottom
R53  DNI  [0402]  34.99 34.28 270 bottom
R54  10K  [0402]  20.02 3.2 90 top
R55  10K  [0402]  19.38 8.58 90 top
R56  10K  [0402]  24.54 15.75 270 top
R57  4.7K  [0402]  20.89 8.58 90 top
R58  10K  [0402]  22.88 61.15 180 top
R59  10K  [0402]  54.79 61.84 180 bottom
R60  10K  [0402]  28.49 35.62 90 bottom
R61  DNI  [0402]  37.3 10.3 90 bottom
R62  10K  [0402]  34.18 40.45 180 bottom
R63  DNI  [0402]  31.72 41.94 270 bottom
R64  10K  [0402]  32.61 41.94 90 bottom
R65  10K  [0402]  21.12 1.89 180 bottom
R66  DNI  [0402]  20.3 7.91 90 bottom
R67  DNI  [0402]  49.77 20.31 270 top
R68  47  [0402]  7.97 29.83 90 bottom
R69  47  [0402]  7.69 39.43 270 bottom
R70  47  [0402]  9.21 35.47 90 bottom
R71  47  [0402]  8.37 35.47 90 bottom
R72  47  [0402]  7.54 35.47 90 bottom
R73  47  [0402]  5.91 35.47 90 bottom
R74  47  [0402]  5.05 33.64 270 bottom
R75  47  [0402]  5.12 35.47 90 bottom
R76  47  [0402]  6.06 39.43 270 bottom
R77  47  [0402]  5.1 29.83 90 bottom
R78  47  [0402]  5.27 39.43 270 bottom
R79  47  [0402]  4.31 29.83 90 bottom
R80  47  [0402]  4.46 39.43 270 bottom
R81  47  [0402]  3.5 29.83 90 bottom
R82  47  [0402]  4.28 35.47 90 bottom
R83  47  [0402]  7.48 33.64 270 bottom
R84  47  [0402]  4.23 33.64 270 bottom
R85  47  [0402]  5.86 33.64 270 bottom
R86  47  [0402]  3.45 35.47 90 bottom
R87  47  [0402]  3.45 33.64 270 bottom
R88  47  [0402]  6.67 33.64 270 bottom
R89  47  [0402]  6.85 39.43 270 bottom
R90  47  [0402]  5.91 29.83 90 bottom
R91  47  [0402]  6.72 35.47 90 bottom
R92  47  [0402]  8.5 39.43 270 bottom
R93  49.9  [0402]  9.14 33.65 270 bottom
R94  49.9  [0402]  8.35 33.65 270 bottom
R95  10K  [0402]  3.27 39.43 90 bottom
R96  240,1%  [0402]  8.29 41.05 0 top
R97  240,1%  [0402]  7.13 29.5 180 top
R98  10K  [0402]  8.78 29.83 270 bottom
R99  1K  [0402]  17.64 33.31 270 bottom
R100  1K  [0402]  17.04 31.31 90 bottom
R101  47  [0402]  8.32 7.4 90 bottom
R102  47  [0402]  7.56 16.9 270 bottom
R103  47  [0402]  9.21 13.2 90 bottom
R104  47  [0402]  8.42 13.2 90 bottom
R105  47  [0402]  7.61 13.2 90 bottom
R106  47  [0402]  6.04 13.2 90 bottom
R107  47  [0402]  5.22 11.52 270 bottom
R108  47  [0402]  5.22 13.2 90 bottom
R109  47  [0402]  5.91 16.9 270 bottom
R110  47  [0402]  5.38 7.4 90 bottom
R111  47  [0402]  5.1 16.9 270 bottom
R112  47  [0402]  4.59 7.4 90 bottom
R113  47  [0402]  4.28 16.9 270 bottom
R114  47  [0402]  3.8 7.4 90 bottom
R115  47  [0402]  4.44 13.2 90 bottom
R116  47  [0402]  7.61 11.52 270 bottom
R117  47  [0402]  4.44 11.52 270 bottom
R118  47  [0402]  6.04 11.52 270 bottom
R119  47  [0402]  3.65 13.2 90 bottom
R120  47  [0402]  3.65 11.52 270 bottom
R121  47  [0402]  6.82 11.52 270 bottom
R122  47  [0402]  6.75 16.9 270 bottom
R123  47  [0402]  6.16 7.4 90 bottom
R124  47  [0402]  6.82 13.2 90 bottom
R125  47  [0402]  8.37 16.9 270 bottom
R126  49.9  [0402]  9.21 11.52 270 bottom
R127  49.9  [0402]  8.42 11.52 270 bottom
R128  10K  [0402]  3.47 16.9 90 bottom
R129  240,1%  [0402]  8.25 7.25 0 top
R130  240,1%  [0402]  8.17 18.48 180 top
R131  10K  [0402]  9.14 7.4 270 bottom
R132  22  [0402]  39.14 15.34 270 bottom
R133  22  [0402]  38 14.96 180 top
R134  22  [0402]  37.99 13.19 180 top
R135  22  [0402]  37.99 15.35 270 bottom
R136  22  [0402]  38 15.85 180 top
R137  22  [0402]  38 10.6 180 top
R138  22  [0402]  37.99 12.3 180 top
R139  22  [0402]  37.99 14.07 180 top
R140  22  [0402]  37.99 11.4 180 top
R141  22  [0402]  38 9.82 180 top
R142  DNI  [0402]  37.98 13.65 90 bottom
R143  10K  [0402]  39.13 13.65 90 bottom
R144  47K  [0402]  36.24 15.85 0 top
R145  47K  [0402]  36.24 14.96 0 top
R146  47K  [0402]  36.24 10.6 0 top
R147  47K  [0402]  36.24 12.3 0 top
R148  47K  [0402]  36.24 14.08 0 top
R149  47K  [0402]  36.24 11.41 0 top
R150  47K  [0402]  36.24 13.19 0 top
R151  47K  [0402]  36.24 9.83 0 top
R152  DNI  [0402]  27.38 9.94 270 bottom
R153  DNI  [0402]  33.31 12.75 90 bottom
R154  4.7K  [0402]  11.08 4.03 270 top
R155  4.7K  [0402]  12.93 4.03 270 top
R156  4.7K  [0402]  15.81 4.03 270 top
R157  10K  [0402]  32.44 12.75 90 bottom
R158  4.7K  [0402]  16.83 4.03 270 top
R159  DNI  [0402]  33.75 6.76 270 bottom
R160  0  [0402]  32.73 6.77 90 bottom
R161  10K  [0402]  36.67 3.86 90 top
R162  0  [0402]  35.4 6.77 90 bottom
R163  22  [0402]  35.78 3.86 90 top
R164  1M  [0402]  36.29 6.77 90 bottom
R165  22  [0402]  34.96 12.7 90 bottom
R166  22  [0402]  14.78 4.03 270 top
R167  4.7K  [0402]  10.16 4.03 270 top
R168  0  [0402]  34.57 6.76 270 bottom
R169  22  [0402]  13.82 4.03 270 top
R170  DNI  [0402]  37.18 6.77 270 bottom
R171  22  [0402]  11.96 4.03 270 top
R172  DNI  [0402]  29.05 15.78 270 top
R173  22  [0402]  21.02 15.78 270 top
R174  22  [0402]  25.34 15.75 270 top
R175  22  [0402]  26.37 15.76 270 top
R176  0  [0402]  43.78 29.53 0 top
R177  22  [0402]  43.83 30.32 0 top
R178  22  [0402]  43.83 31.89 0 top
R179  22  [0402]  43.83 31.1 0 top
R180  22  [0402]  43.79 27.04 0 top
R181  22  [0402]  43.78 28.73 0 top
R182  10K  [0402]  41.22 23.23 180 bottom
R183  DNI  [0402]  41.22 24.04 0 bottom
R184  10K  [0402]  46.65 20.1 180 top
R185  DNI  [0402]  48.38 20.41 180 top
R186  10  [0402]  38.65 8.93 0 bottom
R187  10  [0402]  45.17 29 90 top
R188  22  [0402]  43.79 27.85 0 top
R189  DNI  [0402]  41.5 13.82 180 bottom
R190  DNI  [0402]  44.77 22.62 90 top
R191  10K  [0402]  44.77 24.3 90 top
R192  DNI  [0402]  38.65 7.35 180 bottom
R193  10K  [0402]  43.5 13.82 0 bottom
R194  DNI  [0402]  43.22 21.4 90 top
R195  10K  [0402]  38.64 6.52 180 bottom
R196  10K  [0402]  43.22 23.08 90 top
R197  DNI  [0402]  48.38 21.22 180 top
R198  10K  [0402]  46.63 21.22 180 top
R199  DNI  [0402]  48.38 22.09 180 top
R200  10K  [0402]  46.63 22.09 180 top
R201  DNI  [0402]  48.38 22.87 180 top
R202  10K  [0402]  46.63 22.87 180 top
R203  10K  [0402]  48.38 23.71 180 top
R204  DNI  [0402]  46.63 23.71 180 top
R205  DNI  [0402]  48.38 24.57 180 top
R206  10K  [0402]  46.63 24.57 180 top
R207  DNI  [0402]  41.27 25.51 90 bottom
R208  10K  [0402]  40.48 25.51 270 bottom
R209  22  [0402]  26.72 15.64 270 bottom
R210  22  [0402]  30.83 15.65 270 bottom
R211  22  [0402]  28.01 15.75 270 top
R212  DNI  [0402]  54.07 50.84 180 bottom
R213  22  [0402]  27.18 15.74 270 top
R214  DNI  [0402]  54.07 51.63 0 bottom
R215  22  [0402]  27.56 15.64 270 bottom
R216  DNI  [0402]  52.09 51.63 0 bottom
R217  DNI  [0402]  52.09 50.76 180 bottom
R218  DNI  [0402]  48.38 25.36 180 top
R219  10K  [0402]  46.94 26.38 90 top
R220  10K  [0402]  40.28 27.55 180 bottom
R221  DNI  [0402]  40.28 26.76 0 bottom
R222  10K  [0402]  45.94 27.27 270 top
R223  DNI  [0402]  45.13 27.27 90 top
R224  10K  [0402]  37.96 28.44 270 bottom
R225  DNI  [0402]  37.15 28.44 90 bottom
R226  DNI  [0402]  23.84 1.75 180 bottom
R227  1K  [0402]  20.03 1.21 270 top
R228  1K  [0402]  20.9 1.21 270 top
R229  1K  [0402]  21.79 1.22 270 top
R230  DNI  [0402]  34.75 2.28 0 bottom
R231  DNI  [0402]  23.84 0.86 180 bottom
R232  DNI  [0402]  23.84 3.53 180 bottom
R233  DNI  [0402]  23.84 2.64 180 bottom
R234  DNI  [0402]  34.75 3.17 180 bottom
R235  DNI  [0402]  23.84 5.31 180 bottom
R236  0  [0402]  23.84 4.42 180 bottom
R237  10K  [0402]  42.14 6 0 top
R238  10K  [0402]  39.8 6 0 top
R239  10K  [0402]  44.16 6 0 top
R240  22  [0402]  43.83 32.75 0 top
R241  22  [0402]  43.83 34.59 0 top
R242  22  [0402]  32.66 19.85 270 bottom
R243  22  [0402]  34.26 18.71 270 bottom
R244  2.2K  [0402]  25.16 18.2 90 bottom
R245  2.2K  [0402]  26.13 18.2 90 bottom
R246  2.2K  [0402]  34.75 5.2 0 bottom
R247  2.2K  [0402]  34.75 4.06 0 bottom
R248  22  [0402]  28.4 15.65 270 bottom
R249  22  [0402]  30.02 15.65 270 bottom
R250  22  [0402]  19.45 15.79 270 top
R251  22  [0402]  20.89 17.99 270 bottom
R252  100  [0402]  29.35 41.34 180 top
R253  22  [0402]  21.8 15.78 270 top
R254  22  [0402]  29.21 15.65 270 bottom
R255  22  [0402]  22.61 15.79 270 top
R256  22  [0402]  18.66 15.79 270 top
R257  22  [0402]  20.25 15.78 270 top
R258  22  [0402]  23.43 15.8 270 top
R259  1.5K  [0402]  40.4 30.26 0 bottom
R260  22  [0402]  40.4 31.05 0 bottom
R261  22  [0402]  43.79 37.25 0 top
R262  22  [0402]  44.85 38.49 0 top
R263  22  [0402]  47.11 38.49 0 top
R264  22  [0402]  49.6 36.82 270 top
R265  22  [0402]  50.39 36.82 270 top
R266  22  [0402]  40.4 31.86 0 bottom
R267  22  [0402]  43.79 36.41 0 top
R268  22  [0402]  48.79 36.82 270 top
R269  22  [0402]  51.17 36.82 270 top
R270  22  [0402]  51.99 36.82 270 top
R271  22  [0402]  52.82 36.82 270 top
R272  2.49K 1%  [0402]  54.53 27.1 90 top
R273  4.7K  [0402]  48.8 26.64 90 top
R274  4.7K  [0402]  49.69 26.64 90 top
R275  4.7K  [0402]  49.69 41.72 90 top
R276  4.7K  [0402]  53.65 36.82 270 top
R277  4.7K  [0402]  46.97 29.82 90 top
R278  4.7K  [0402]  45.57 36.44 180 top
R279  DNI  [0402]  43.79 35.55 180 top
R280  4.7K  [0402]  45.57 37.25 180 top
R281  4.7K  [0402]  46.97 36.81 90 top
R282  4.7K  [0402]  47.82 36.82 90 top
R283  DNI  [0402]  47.91 26.64 90 top
R284  4.7K  [0402]  46.99 28.09 90 top
R285  4.7K  [0402]  45.53 32.98 90 top
R286  DNI  [0402]  43.83 33.74 180 top
R287  4.7K  [0402]  46.16 34.74 270 top
R288  DNI  [0402]  45.35 34.74 90 top
R289  22  [0402]  41.99 13.48 0 top
R290  22  [0402]  39.82 13.02 0 top
R291  22  [0402]  43.24 15.41 0 top
R292  22  [0402]  43.23 16.31 0 top
R293  22  [0402]  40.3 15.56 270 top
R294  22  [0402]  41.09 15.56 270 top
R295  22  [0402]  39.26 18.81 0 bottom
R296  22  [0402]  43.25 17.99 0 top
R297  22  [0402]  43.26 19.66 0 top
R298  22  [0402]  43.24 17.18 0 top
R299  22  [0402]  39.23 19.65 0 bottom
R300  22  [0402]  43.24 18.82 0 top
R301  2.49K 1%  [0402]  52.71 9.32 90 top
R302  4.7K  [0402]  46.29 8.94 90 top
R303  4.7K  [0402]  47.28 8.94 90 top
R304  4.7K  [0402]  51.38 21.96 180 top
R305  4.7K  [0402]  54.3 17.58 180 top
R306  4.7K  [0402]  44.33 8.9 90 top
R307  4.7K  [0402]  44.91 15.41 180 top
R308  DNI  [0402]  43.24 14.54 180 top
R309  4.7K  [0402]  44.92 16.31 180 top
R310  4.7K  [0402]  45.94 18.8 270 top
R311  4.7K  [0402]  47.06 18.8 270 top
R312  4.7K  [0402]  45.2 8.9 270 top
R313  DNI  [0402]  44.76 7.63 180 top
R314  DNI  [0402]  39.72 11.39 0 top
R315  4.7K  [0402]  41.98 12.69 180 top
R316  4.7K  [0402]  44.19 13.26 90 top
R317  DNI  [0402]  43.3 13.26 270 top
R318  DNI  [0402]  31.03 21.1 0 bottom
R319  0  [0402]  55.52 58.84 90 top
R320  DNI  [0402]  19.72 15.87 270 bottom
R321  0  [0402]  20.55 15.87 270 bottom
R322  22  [0402]  25.49 15.65 270 bottom
R323  1K  [0402]  54.07 53.33 180 bottom
R324  10K  [0402]  54.06 52.46 180 bottom
R326  100K  [0402]  54.22 57.11 0 bottom
R327  1K  [0402]  52.09 53.35 0 bottom
R329  10K  [0402]  52.09 52.46 0 bottom
TP1  TP1mm  [TP_SMD1MMCIRCLE]  53.83 62.66 0 top
TP2  TP1mm  [TP_SMD1MMCIRCLE]  12.06 54.6 90 top
TP3  TP1mm  [TP_SMD1MMCIRCLE]  16.04 65.19 90 top
TP4  TP1mm  [TP_SMD1MMCIRCLE]  13.66 53.33 0 top
TP5  TP1mm  [TP_SMD1MMCIRCLE]  37.71 45.73 0 top
TP6  TP1mm  [TP_SMD1MMCIRCLE]  40.94 53.25 0 top
TP7  TP1mm  [TP_SMD1MMCIRCLE]  43.88 54.5 0 top
TP8  TP1mm  [TP_SMD1MMCIRCLE]  10.56 52.41 0 top
TP9  TP1mm  [TP_SMD1MMCIRCLE]  23.94 54.45 0 top
TP10  TP1mm  [TP_SMD1MMCIRCLE]  15.13 53.25 0 top
TP11  TP1mm  [TP_SMD1MMCIRCLE]  19.88 66.13 0 top
TP12  TP1mm  [TP_SMD1MMCIRCLE]  55.57 57.37 0 top
TP13  TP1mm  [TP_SMD1MMCIRCLE]  16.02 63.67 0 top
TP14  TP1mm  [TP_SMD1MMCIRCLE]  43.45 61.68 0 top
TP15  TP1mm  [TP_SMD1MMCIRCLE]  43.86 55.94 0 top
TP16  TP1mm  [TP_SMD1MMCIRCLE]  42.41 52.87 0 top
TP17  TP1mm  [TP_SMD1MMCIRCLE]  43.88 52.92 0 top
TP18  TP1mm  [TP_SMD1MMCIRCLE]  16.88 52.92 90 top
TP19  TP1mm  [TP_SMD1MMCIRCLE]  49.85 50.28 0 top
TP20  TP1mm  [TP_SMD1MMCIRCLE]  48.56 49.85 0 top
TP21  TP1mm  [TP_SMD1MMCIRCLE]  23.49 48.96 0 top
TP22  TP1mm  [TP_SMD1MMCIRCLE]  21.89 48.93 0 top
TP23  TP1mm  [TP_SMD1MMCIRCLE]  16.95 56.98 0 top
TP24  TP1mm  [TP_SMD1MMCIRCLE]  39.79 56.12 0 top
TP25  TP1mm  [TP_SMD1MMCIRCLE]  43.58 60.13 0 top
TP27  TP1mm  [TP_SMD1MMCIRCLE]  55.59 60.9 0 top
TP28  TP1mm  [TP_SMD1MMCIRCLE]  34.81 16.05 0 top
TP29  TP1mm  [TP_SMD1MMCIRCLE]  33.32 14.75 0 top
TP30  TP1mm  [TP_SMD1MMCIRCLE]  31.83 14.8 0 top
TP31  TP1mm  [TP_SMD1MMCIRCLE]  30.28 16.02 0 top
TP32  TP1mm  [TP_SMD1MMCIRCLE]  30.41 14.75 0 top
TP33  TP1mm  [TP_SMD1MMCIRCLE]  19.87 12.63 0 top
TP34  TP1mm  [TP_SMD1MMCIRCLE]  33.32 16.07 0 top
TP35  TP1mm  [TP_SMD1MMCIRCLE]  31.83 16.07 0 top
U1  TPS3808G50QDBVRCT  [SOT-23-6]  46.88 53.96 270 top
U2  NCP51200MNTXG  [10-DFN]  12.41 62.24 0 top
U3  TPS6590379ZWSR  [NFBGA_ZWS_169]  30.74 55.42 270 top
U4  SN74LVC1G07DBVR  [SOT-23-5]  44.21 50.43 270 top
U5  SN74LVC1G08DBVR  [SOT-23-5]  19.42 5.95 90 top
U6  AM5728BABCXEA  [760-FCBGA]  30.27 28.77 180 top
U7  SN74LVC1G07DBVR  [SOT-23-5]  20.68 4.61 180 bottom
U8  MT41K256M16TW-107 AAT:P  [96-TFBGA]  9.93 45.81 270 top
U9  MT41K256M16TW-107 AAT:P  [96-TFBGA]  9.93 34.61 270 top
U10  MT41K256M16TW-107 AAT:P  [96-TFBGA]  9.93 12.21 270 top
U11  MT41K256M16TW-107 AAT:P  [96-TFBGA]  9.93 23.41 270 top
U12  MTFC16GAPALBH-AAT  [153-TFBGA]  28.29 8.16 270 top
U13  RV-3129-C3-32.768KHZ-OPTION-A-TB-QA  [RV-3129-C3]  34.77 9.79 270 bottom
U14  SN74AXC1T45QDCKRQ1  [SC-70-6]  36.59 6.38 180 top
U15  IS25LP016D-JBLA3  [8-SOIC_5P3MM]  42.46 8.19 270 bottom
U16  CAV24C08WE-GT3  [8-SOIC_3P9MM]  29.05 3.28 90 bottom
U17  RTL8211FSI-VS-CG  [QFN48]  51.33 31.49 180 top
U18  SN74LVC1G08DBVR  [SOT-23-5]  52.3 41.64 270 top
U19  RTL8211FSI-VS-CG  [QFN48]  49.49 13.96 180 top
U20  SN74LVC1G08DBVR  [SOT-23-5]  52.31 19.84 270 top
XP1  SODIMM-204 PCB Gold Fingers Edge Connector  [SODIMM-204]  58.63 2.18 90 top
Y1  ECS-163.8-12-33Q-JES-TR  [XTAL4_3P2X2P5_SMD]  40.48 60.1 270 bottom
Y2  TSX-3225 20.0000MF20G-AC3  [XTAL4_3P2X2P5_SMD]  28.92 42.54 180 bottom
Y3  DNI  [XTAL4_3P2X2P5_SMD]  35.17 42.56 0 bottom
Y4  FL2500316Z  [XTAL4_3P2X2P5_SMD]  52.11 24.7 180 top
Y5  FL2500316Z  [XTAL4_3P2X2P5_SMD]  50.12 7.59 180 top

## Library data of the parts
C1 C12 C13 C17 C22 C55 C56 C59 C61 C63-C65 C82-C85 C87-C93 C95 C96 C98 C100 C101 C118-C122 C124-C143 C145 C147-C151 C153-C157 C159 C165 C166 C171 C173 C178 C179 = CAP_0.1uF_X7R_16V_10% 0402
C2 C3 C8-C11 C42 C52 C80 C86 C117 C123 C160 = CAP_10uF_X5R_6.3V_20%_0603
C4 C6 = CAP_4.7uF_X5R_6.3V_20%_0402: Tolerance: TOL*; User Part Number: P/N*
C5 C161 C164 = CAP_0.001_X7R_50V_10%_0402
C7 = 1C_0.01uFCapacitor16V10%0402
C14 C188 C191 = C_12pF/0402/50V_COG_0402
C15 C207 C209 = C_12pF/0402/50V_COG_0402: signal model: CAP_0.1UF_X7R_16V_10%_0402__402_0.1uf_16V
C16 = CAP_2.2uF_X5R_6.3V_10%_0402: signal model: CAP_0.1UF_X7R_16V_10%_0402__402_0.1uf_16V
C18 C21 C23 C25 C27 C32 C33 C37 C45 = CAP_4.7uF_X5R_6.3V_20%_0402
C19 C20 C24 C39 = CAP_47uF_X5R_6.3V_20%_1206: Tolerance: TOL*; User Part Number: P/N*
C26 C28 C29 C47 = CAP_47uF_X5R_6.3V_20% 0805: Tolerance: TOL*; User Part Number: P/N*
C30 = CAP_47uF_X5R_6.3V_20% 0805: Tolerance: TOL*; User Part Number: P/N*; signal model: CAP_0.1UF_X7R_16V_10%_0402__402_0.1uf_16V
C31 C34-C36 C38 C40 C41 C43 C44 C46 C48-C51 = CAP_2.2uF_X5R_6.3V_10%_0402
C53 C102 C162 C163 = CAP_0.1uF_X5R_6.3V_20% 0201
C54 C62 C158 C177 C180-C187 C189 C190 C192-C197 C200-C205 C208 C210 C212 C214 = CAP NP
C57 C58 C60 = CAP_18PF_COG_50V_5%_0402
C66-C79 C103 C106 C107 C109 C112-C116 = CC0402JRX7R7BB104
C81 C94 C97 C99 = CAP_0.1uF_X7R_16V_10% 0402: signal model: CAP_0.1UF_X7R_16V_10%_0402__402_0.1uf_16V
C104 C105 C108 C110 C111 = CC0402JRX7R7BB104: signal model: CAP_0.1UF_X7R_16V_10%_0402__402_0.1uf_16V
C144 C152 = 1C_2.2uF16V10%SMD0805
C146 = CGB2A1X5R1E105K033BC
C167-C170 C172 C174-C176 = CAP_0.1uF_X7R_16V_10% 0402: signal model: CAP_0.1UF_X7R_16V_10%_0402__040_0.1uF
C198 C199 C218-C220 C223 C226 C229 C232-C238 C243 C246 C249-C251 C254-C257 C260 C261 C263 C267-C269 C271 C273 C275-C282 C285-C293 C295 C296 C299-C305 C307-C309 C311-C315 C317 = CC0402KRX7R7BB103
C206 C211 C213 C215 C216 = CAP NP: signal model: CAP_0.1UF_X7R_16V_10%_0402__402_0.1uf_16V
C217 C227 C240 C245 C265 C266 C283 C284 C294 C297 C298 C306 C310 C316 C318 = CL21A106KOQNNNG
C221 C222 C224 C225 C228 C230 C231 C241 C242 C247 C248 C258 C259 C262 C270 C272 C274 = CC0402KRX7R7BB103: signal model: CAP_0.1UF_X7R_16V_10%_0402__402_0.1uf_16V
C239 C244 C252 C253 C264 = CL21A106KOQNNNG: signal model: CAP_0.1UF_X7R_16V_10%_0402__402_0.1uf_16V
C319-C333 = CAP_1.0UF_X5R_4V_20%_0201
D1 D4-D7 = LED_LTST_C150GKT
D2 D3 = TLVH431_0: User Part Number: P/N*; Tolerance: TOL*
L1-L3 L8 L13 L19 = IND_PWR_1.0uH_4.2A_SMD
L4-L7 L9 = IND_PWR_1.0uH_2.7A_SMD
L10-L12 L14-L18 L20 L21 = BLM18BB100SN1D
L22-L24 = 1L_NFM21PC474_EMIFilter_0
MH1-MH6 = TESTPOINT
P1 = HDR_JTAG_20P
Q1 Q2 = 1Q_MOSFET_PChan_FDT434P_0
Q3-Q8 = 1Q_MOSFET_NChan_BSS138_0: User Part Number: P/N*; Tolerance: TOL*
R1 R3 = RMCF0402FT499R
R2 R7 R13 R20 R21 R24 R27 R31 R35-R38 R40-R42 R46 R48 R49 R56 R59 R60 R230 R320 R321 = RES_10K_1/16W_1%_0402
R4 R9 R23 R99 R100 R227-R229 R318 R323 R326 R327 = RES_1K_1/16W_5%_0402
R5 R6 R10 R12 R33 R34 R55 R65 R66 R95 R98 R183 R184 R187 R189 R191 R193 R195 R196 R198 R200 R202 R204 R206 R208 R214 R217 R219 R221 R225 R234 = RMCF0402FT10K0
R8 = 1R_47KOhmResistor1/16W0402
R11 R58 R237-R239 = RES_100K_1/16W_1%_0402
R14 R15 = 1R_ZeroOhmResistor1/16W0402
R16 R17 = RMCF0402FT24K3
R18 R19 R22 R25 R26 R43 R51 R67 R246 R247 = RES_DNI_1/16W_1%_0402
R28 = 1R_10KOhmResistor1/16W0402
R29 R30 R32 R39 = RES_10K_1/16W_1%_0402: signal model: RES_0_1/16W_1%_0402_402_0_1%_0_1%
R44 R45 R50 R62 R159-R162 R168 R170 R226 R231-R233 R235 R236 = RES_0_1/16W_1%_0402
R47 = 1R_1KOhmResistor1/16W0402
R52 R245 = RES_2.2K_1/16W_1%_0402
R53 = RES_DNI_1/16W_1%_0402: signal model: RES_0_1/16W_1%_0402_402_0_1%_0_1%
R54 R259 R272-R288 R301 R303-R317 = RESISTOR
R57 = 1R_4.7KOhmResistor1/16W0402: signal model: RES_0_1/16W_1%_0402_402_0_1%_0_1%
R61 = RES_10K_1/16W_1%_0402: signal model: RES_22_1/16W_5%_0402_402_22_5%_22_5%
R63 = RES_DNI_1/16W_1%_0402: signal model: RES_22_1/16W_5%_0402_402_22_5%_22_5%
R64 = RES_0_1/16W_1%_0402: signal model: RES_22_1/16W_5%_0402_402_22_5%_22_5%
R68-R77 R90-R92 R101-R104 R116 R117 R119-R122 = 1R_47ohm1/16W1%smd0402
R78-R83 R105-R110 R124 R125 = 1R_47ohm1/16W1%smd0402: signal model: RES_22_1/16W_5%_0402_402_22_5%_22_5%
R84-R89 R111-R115 R118 R123 = 1R_47ohm1/16W1%smd0402: signal model: RES_0_1/16W_1%_0402_402_0_1%_0_1%
R93 R94 = 1R_49.9OhmResistor1/16W0402
R96 = RES_240_1/16W_1%_0402: signal model: RES_0_1/16W_1%_0402_402_0_1%_0_1%
R97 = RES_240_1/16W_1%_0402
R126 R127 = 1R_49.9OhmResistor1/16W0402: signal model: RES_22_1/16W_5%_0402_402_22_5%_22_5%
R128 R131 R223 = RMCF0402FT10K0: signal model: RES_22_1/16W_5%_0402_402_22_5%_22_5%
R129 R130 = RES_240_1/16W_1%_0402: signal model: RES_22_1/16W_5%_0402_402_22_5%_22_5%
R132-R136 R138-R141 = RES_22_1/16W_5%_0402: signal model: RES_22_1/16W_5%_0402_402_22_5%_22_5%
R137 R260-R271 R289 R292-R300 = RES_22_1/16W_5%_0402: signal model: RES_22_1/16W_5%_0402_0402_22_22
R142-R150 R152 = RES_47K_1/16W_1%_0402: signal model: RES_22_1/16W_5%_0402_402_22_5%_22_5%
R151 = RES_47K_1/16W_1%_0402
R153 = RES_4.75K_1/16W_1%_0402: signal model: RES_22_1/16W_5%_0402_402_22_5%_22_5%
R154-R156 R158 R167 = RES_4.7K_1/16W_5%_0402
R157 R164 R319 = RES_4.75K_1/16W_1%_0402
R163 R165 R166 R169 R171-R181 R188 R209-R211 R213 R215 R240-R243 R248 R250 R251 R253-R258 R322 = RES_22_1/16W_5%_0402
R182 R185 R190 R194 R197 R199 R201 R203 R205 R207 R212 R216 R218 R220 R222 R224 R324 R329 = 1R_18KohmResistor1/10W1%smd0402
R186 = RMCF0402FT10K0: signal model: RMCF0402FT10K0_0402_10__10
R192 = RMCF0402FT10K0: signal model: RMCF0402FT10K0_0402_DNI__DNI
R244 = RES_2.2K_1/16W_1%_0402: signal model: RES_0_1/16W_1%_0402_402_0_1%_0_1%
R249 R290 R291 = RES_22_1/16W_5%_0402: signal model: RES_0_1/16W_1%_0402_402_0_1%_0_1%
R252 = RES_100_1/10W_5%_0402
R302 = RESISTOR: signal model: RES_0_1/16W_1%_0402_402_0_1%_0_1%
TP1-TP3 TP5 TP8 TP11-TP25 TP27-TP35 = 2H_TestPointThroughHole
TP4 TP6 TP7 TP9 TP10 = 2H_Testpoint_SMD1mmCircle
U1 = TPS3808
U2 = NCP51200MNTXG: User Part Number: X; Tolerance: X
U3 = IC_TPS659039_8
U4 U7 = SN74LVC1G07DBVR
U5 U18 U20 = SN74LVC1G08DBVR
U6 = IC_AM572x_BGA_36
U8-U11 = MEM_DDR3L_256MBx16_0
U12 = MTFC16GAPALBH-AAT
U13 = RV-3129-C3
U14 = SN74AXC1T45QDCKRQ1
U15 = IS25LP016D-JBLA3
U16 = CAV24C08WE-GT3
U17 U19 = RTL8211FSI-VS-CG
XP1 = CL-SOM-AM5728_XS1_0
Y1-Y5 = CRYS_24MHz_SCC

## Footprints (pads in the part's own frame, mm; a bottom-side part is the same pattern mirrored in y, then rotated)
2P0_4P0_MM_PL
  round 4 hole 2.2: 1(0,0)
2P2_5P0_MM_PL
  round 4.826 hole 2.2: 1(0,0)
8-SOIC_3P9MM
  rect 0.61x2.184 smd: 1(-1.905,-2.603)
  oval 0.61x2.184 smd: 2(-0.635,-2.603) 3(0.635,-2.603) 4(1.905,-2.603) 5(1.905,2.603) 6(0.635,2.603) 7(-0.635,2.603) 8(-1.905,2.603)
8-SOIC_5P3MM
  oval 1.6x0.6 smd: 1(-4,1.905) 2(-4,0.635) 3(-4,-0.635) 4(-4,-1.905) 5(4,-1.905) 6(4,-0.635) 7(4,0.635) 8(4,1.905)
10-DFN
  rect 0.305x0.762 smd: 1(-1.001,-1.473) 2(-0.5,-1.473) 3(0,-1.473) 4(0.5,-1.473) 5(1.001,-1.473) 6(1.001,1.473) 7(0.5,1.473) 8(0,1.473) 9(-0.5,1.473) 10(-1.001,1.473)
  custom 0.406x0.406 smd: 11(0,0)
96-TFBGA
  round 0.42 smd: A1(-3.2,6) A2(-2.4,6) A3(-1.6,6) A7(1.6,6) A8(2.4,6) A9(3.2,6) B1(-3.2,5.2) B2(-2.4,5.2) B3(-1.6,5.2) B7(1.6,5.2) B8(2.4,5.2) B9(3.2,5.2) C1(-3.2,4.4) C2(-2.4,4.4) C3(-1.6,4.4) C7(1.6,4.4) C8(2.4,4.4) C9(3.2,4.4) D1(-3.2,3.6) D2(-2.4,3.6) D3(-1.6,3.6) D7(1.6,3.6) D8(2.4,3.6) D9(3.2,3.6) E1(-3.2,2.8) E2(-2.4,2.8) E3(-1.6,2.8) E7(1.6,2.8) E8(2.4,2.8) E9(3.2,2.8) F1(-3.2,2) F2(-2.4,2) F3(-1.6,2) F7(1.6,2) F8(2.4,2) F9(3.2,2) G1(-3.2,1.2) G2(-2.4,1.2) G3(-1.6,1.2) G7(1.6,1.2) G8(2.4,1.2) G9(3.2,1.2) H1(-3.2,0.4) H2(-2.4,0.4) H3(-1.6,0.4) H7(1.6,0.4) H8(2.4,0.4) H9(3.2,0.4) J1(-3.2,-0.4) J2(-2.4,-0.4) J3(-1.6,-0.4) J7(1.6,-0.4) J8(2.4,-0.4) J9(3.2,-0.4) K1(-3.2,-1.2) K2(-2.4,-1.2) K3(-1.6,-1.2) K7(1.6,-1.2) K8(2.4,-1.2) K9(3.2,-1.2) L1(-3.2,-2) L2(-2.4,-2) L3(-1.6,-2) L7(1.6,-2) L8(2.4,-2) L9(3.2,-2) M1(-3.2,-2.8) M2(-2.4,-2.8) M3(-1.6,-2.8) M7(1.6,-2.8) M8(2.4,-2.8) M9(3.2,-2.8) N1(-3.2,-3.6) N2(-2.4,-3.6) N3(-1.6,-3.6) N7(1.6,-3.6) N8(2.4,-3.6) N9(3.2,-3.6) P1(-3.2,-4.4) P2(-2.4,-4.4) P3(-1.6,-4.4) P7(1.6,-4.4) P8(2.4,-4.4) P9(3.2,-4.4) R1(-3.2,-5.2) R2(-2.4,-5.2) R3(-1.6,-5.2) R7(1.6,-5.2) R8(2.4,-5.2) R9(3.2,-5.2) T1(-3.2,-6) T2(-2.4,-6) T3(-1.6,-6) T7(1.6,-6) T8(2.4,-6) T9(3.2,-6)
153-TFBGA
  round 0.3 smd: A1(-3.25,3.25) A2(-2.75,3.25) A3(-2.25,3.25) A4(-1.75,3.25) A5(-1.25,3.25) A6(-0.75,3.25) A7(-0.25,3.25) A8(0.25,3.25) A9(0.75,3.25) A10(1.25,3.25) A11(1.75,3.25) A12(2.25,3.25) A13(2.75,3.25) A14(3.25,3.25) B1(-3.25,2.75) B2(-2.75,2.75) B3(-2.25,2.75) B4(-1.75,2.75) B5(-1.25,2.75) B6(-0.75,2.75) B7(-0.25,2.75) B8(0.25,2.75) B9(0.75,2.75) B10(1.25,2.75) B11(1.75,2.75) B12(2.25,2.75) B13(2.75,2.75) B14(3.25,2.75) C1(-3.25,2.25) C2(-2.75,2.25) C3(-2.25,2.25) C4(-1.75,2.25) C5(-1.25,2.25) C6(-0.75,2.25) C7(-0.25,2.25) C8(0.25,2.25) C9(0.75,2.25) C10(1.25,2.25) C11(1.75,2.25) C12(2.25,2.25) C13(2.75,2.25) C14(3.25,2.25) D1(-3.25,1.75) D2(-2.75,1.75) D3(-2.25,1.75) D4(-1.75,1.75) D12(2.25,1.75) D13(2.75,1.75) D14(3.25,1.75) E1(-3.25,1.25) E2(-2.75,1.25) E3(-2.25,1.25) E5(-1.25,1.25) E6(-0.75,1.25) E7(-0.25,1.25) E8(0.25,1.25) E9(0.75,1.25) E10(1.25,1.25) E12(2.25,1.25) E13(2.75,1.25) E14(3.25,1.25) F1(-3.25,0.75) F2(-2.75,0.75) F3(-2.25,0.75) F5(-1.25,0.75) F10(1.25,0.75) F12(2.25,0.75) F13(2.75,0.75) F14(3.25,0.75) G1(-3.25,0.25) G2(-2.75,0.25) G3(-2.25,0.25) G5(-1.25,0.25) G10(1.25,0.25) G12(2.25,0.25) G13(2.75,0.25) G14(3.25,0.25) H1(-3.25,-0.25) H2(-2.75,-0.25) H3(-2.25,-0.25) H5(-1.25,-0.25) H10(1.25,-0.25) H12(2.25,-0.25) H13(2.75,-0.25) H14(3.25,-0.25) J1(-3.25,-0.75) J2(-2.75,-0.75) J3(-2.25,-0.75) J5(-1.25,-0.75) J10(1.25,-0.75) J12(2.25,-0.75) J13(2.75,-0.75) J14(3.25,-0.75) K1(-3.25,-1.25) K2(-2.75,-1.25) K3(-2.25,-1.25) K5(-1.25,-1.25) K6(-0.75,-1.25) K7(-0.25,-1.25) K8(0.25,-1.25) K9(0.75,-1.25) K10(1.25,-1.25) K12(2.25,-1.25) K13(2.75,-1.25) K14(3.25,-1.25) L1(-3.25,-1.75) L2(-2.75,-1.75) L3(-2.25,-1.75) L12(2.25,-1.75) L13(2.75,-1.75) L14(3.25,-1.75) M1(-3.25,-2.25) M2(-2.75,-2.25) M3(-2.25,-2.25) M4(-1.75,-2.25) M5(-1.25,-2.25) M6(-0.75,-2.25) M7(-0.25,-2.25) M8(0.25,-2.25) M9(0.75,-2.25) M10(1.25,-2.25) M11(1.75,-2.25) M12(2.25,-2.25) M13(2.75,-2.25) M14(3.25,-2.25) N1(-3.25,-2.75) N2(-2.75,-2.75) N3(-2.25,-2.75) N4(-1.75,-2.75) N5(-1.25,-2.75) N6(-0.75,-2.75) N7(-0.25,-2.75) N8(0.25,-2.75) N9(0.75,-2.75) N10(1.25,-2.75) N11(1.75,-2.75) N12(2.25,-2.75) N13(2.75,-2.75) N14(3.25,-2.75) P1(-3.25,-3.25) P2(-2.75,-3.25) P3(-2.25,-3.25) P4(-1.75,-3.25) P5(-1.25,-3.25) P6(-0.75,-3.25) P7(-0.25,-3.25) P8(0.25,-3.25) P9(0.75,-3.25) P10(1.25,-3.25) P11(1.75,-3.25) P12(2.25,-3.25) P13(2.75,-3.25) P14(3.25,-3.25)
0402
  rect 0.45x0.5 smd: 1(-0.475,0) 2(0.475,0)
0603
  rect 0.889x0.813 smd: 1(-0.762,0) 2(0.762,0)
760-FCBGA
  round 0.4 smd: A1(-10.8,10.8) A2(-10,10.8) A3(-9.2,10.8) A4(-8.4,10.8) A5(-7.6,10.8) A6(-6.8,10.8) A7(-6,10.8) A8(-5.2,10.8) A9(-4.4,10.8) A10(-3.6,10.8) A11(-2.8,10.8) A12(-2,10.8) A13(-1.2,10.8) A14(-0.4,10.8) A15(0.4,10.8) A16(1.2,10.8) A17(2,10.8) A18(2.8,10.8) A19(3.6,10.8) A20(4.4,10.8) A21(5.2,10.8) A22(6,10.8) A23(6.8,10.8) A24(7.6,10.8) A25(8.4,10.8) A26(9.2,10.8) A27(10,10.8) A28(10.8,10.8) AA1(-10.8,-5.2) AA2(-10,-5.2) AA3(-9.2,-5.2) AA4(-8.4,-5.2) AA5(-7.6,-5.2) AA6(-6.8,-5.2) AA7(-6,-5.2) AA8(-5.2,-5.2) AA9(-4.4,-5.2) AA10(-3.6,-5.2) AA11(-2.8,-5.2) AA12(-2,-5.2) AA13(-1.2,-5.2) AA14(-0.4,-5.2) AA15(0.4,-5.2) AA16(1.2,-5.2) AA17(2,-5.2) AA18(2.8,-5.2) AA19(3.6,-5.2) AA20(4.4,-5.2) AA21(5.2,-5.2) AA22(6,-5.2) AA23(6.8,-5.2) AA24(7.6,-5.2) AA25(8.4,-5.2) AA26(9.2,-5.2) AA27(10,-5.2) AA28(10.8,-5.2) AB1(-10.8,-6) AB2(-10,-6) AB3(-9.2,-6) AB4(-8.4,-6) AB5(-7.6,-6) AB6(-6.8,-6) AB7(-6,-6) AB8(-5.2,-6) AB9(-4.4,-6) AB10(-3.6,-6) AB11(-2.8,-6) AB12(-2,-6) AB13(-1.2,-6) AB14(-0.4,-6) AB15(0.4,-6) AB16(1.2,-6) AB17(2,-6) AB18(2.8,-6) AB19(3.6,-6) AB20(4.4,-6) AB21(5.2,-6) AB22(6,-6) AB23(6.8,-6) AB24(7.6,-6) AB25(8.4,-6) AB27(10,-6) AB28(10.8,-6) AC1(-10.8,-6.8) AC2(-10,-6.8) AC3(-9.2,-6.8) AC4(-8.4,-6.8) AC5(-7.6,-6.8) AC6(-6.8,-6.8) AC7(-6,-6.8) AC8(-5.2,-6.8) AC9(-4.4,-6.8) AC10(-3.6,-6.8) AC11(-2.8,-6.8) AC12(-2,-6.8) AC13(-1.2,-6.8) AC14(-0.4,-6.8) AC15(0.4,-6.8) AC16(1.2,-6.8) AC17(2,-6.8) AC18(2.8,-6.8) AC19(3.6,-6.8) AC20(4.4,-6.8) AC21(5.2,-6.8) AC22(6,-6.8) AC23(6.8,-6.8) AC24(7.6,-6.8) AC25(8.4,-6.8) AC26(9.2,-6.8) AC27(10,-6.8) AC28(10.8,-6.8) AD1(-10.8,-7.6) AD2(-10,-7.6) AD3(-9.2,-7.6) AD4(-8.4,-7.6) AD5(-7.6,-7.6) AD6(-6.8,-7.6) AD7(-6,-7.6) AD8(-5.2,-7.6) AD9(-4.4,-7.6) AD10(-3.6,-7.6) AD11(-2.8,-7.6) AD12(-2,-7.6) AD13(-1.2,-7.6) AD14(-0.4,-7.6) AD15(0.4,-7.6) AD16(1.2,-7.6) AD17(2,-7.6) AD18(2.8,-7.6) AD19(3.6,-7.6) AD20(4.4,-7.6) AD21(5.2,-7.6) AD22(6,-7.6) AD23(6.8,-7.6) AD24(7.6,-7.6) AD25(8.4,-7.6) AD26(9.2,-7.6) AD27(10,-7.6) AD28(10.8,-7.6) AE1(-10.8,-8.4) AE2(-10,-8.4) AE3(-9.2,-8.4) AE5(-7.6,-8.4) AE6(-6.8,-8.4) AE7(-6,-8.4) AE8(-5.2,-8.4) AE9(-4.4,-8.4) AE10(-3.6,-8.4) AE11(-2.8,-8.4) AE12(-2,-8.4) AE13(-1.2,-8.4) AE14(-0.4,-8.4) AE15(0.4,-8.4) AE16(1.2,-8.4) AE17(2,-8.4) AE18(2.8,-8.4) AE19(3.6,-8.4) AE20(4.4,-8.4) AE21(5.2,-8.4) AE22(6,-8.4) AE23(6.8,-8.4) AE24(7.6,-8.4) AE26(9.2,-8.4) AE27(10,-8.4) AE28(10.8,-8.4) AF1(-10.8,-9.2) AF2(-10,-9.2) AF3(-9.2,-9.2) AF4(-8.4,-9.2) AF5(-7.6,-9.2) AF6(-6.8,-9.2) AF8(-5.2,-9.2) AF9(-4.4,-9.2) AF11(-2.8,-9.2) AF12(-2,-9.2) AF14(-0.4,-9.2) AF15(0.4,-9.2) AF17(2,-9.2) AF18(2.8,-9.2) AF20(4.4,-9.2) AF21(5.2,-9.2) AF22(6,-9.2) AF23(6.8,-9.2) AF24(7.6,-9.2) AF25(8.4,-9.2) AF26(9.2,-9.2) AF27(10,-9.2) AF28(10.8,-9.2) AG1(-10.8,-10) AG2(-10,-10) AG3(-9.2,-10) AG4(-8.4,-10) AG5(-7.6,-10) AG6(-6.8,-10) AG7(-6,-10) AG8(-5.2,-10) AG9(-4.4,-10) AG10(-3.6,-10) AG11(-2.8,-10) AG12(-2,-10) AG13(-1.2,-10) AG14(-0.4,-10) AG15(0.4,-10) AG16(1.2,-10) AG17(2,-10) AG18(2.8,-10) AG19(3.6,-10) AG20(4.4,-10) AG21(5.2,-10) AG22(6,-10) AG23(6.8,-10) AG24(7.6,-10) AG25(8.4,-10) AG26(9.2,-10) AG27(10,-10) AG28(10.8,-10) AH1(-10.8,-10.8) AH2(-10,-10.8) AH3(-9.2,-10.8) AH4(-8.4,-10.8) AH5(-7.6,-10.8) AH6(-6.8,-10.8) AH7(-6,-10.8) AH8(-5.2,-10.8) AH9(-4.4,-10.8) AH10(-3.6,-10.8) AH11(-2.8,-10.8) AH12(-2,-10.8) AH13(-1.2,-10.8) AH14(-0.4,-10.8) AH15(0.4,-10.8) AH16(1.2,-10.8) AH17(2,-10.8) AH18(2.8,-10.8) AH19(3.6,-10.8) AH20(4.4,-10.8) AH21(5.2,-10.8) AH22(6,-10.8) AH23(6.8,-10.8) AH24(7.6,-10.8) AH25(8.4,-10.8) AH26(9.2,-10.8) AH27(10,-10.8) AH28(10.8,-10.8) B1(-10.8,10) B2(-10,10) B3(-9.2,10) B4(-8.4,10) B5(-7.6,10) B6(-6.8,10) B7(-6,10) B8(-5.2,10) B9(-4.4,10) B10(-3.6,10) B11(-2.8,10) B12(-2,10) B13(-1.2,10) B14(-0.4,10) B15(0.4,10) B16(1.2,10) B17(2,10) B18(2.8,10) B19(3.6,10) B20(4.4,10) B21(5.2,10) B22(6,10) B23(6.8,10) B24(7.6,10) B25(8.4,10) B26(9.2,10) B27(10,10) B28(10.8,10) C1(-10.8,9.2) C2(-10,9.2) C3(-9.2,9.2) C4(-8.4,9.2) C5(-7.6,9.2) C6(-6.8,9.2) C7(-6,9.2) C8(-5.2,9.2) C9(-4.4,9.2) C11(-2.8,9.2) C12(-2,9.2) C14(-0.4,9.2) C15(0.4,9.2) C17(2,9.2) C18(2.8,9.2) C20(4.4,9.2) C21(5.2,9.2) C23(6.8,9.2) C24(7.6,9.2) C25(8.4,9.2) C26(9.2,9.2) C27(10,9.2) C28(10.8,9.2) D1(-10.8,8.4) D2(-10,8.4) D3(-9.2,8.4) D5(-7.6,8.4) D6(-6.8,8.4) D7(-6,8.4) D8(-5.2,8.4) D9(-4.4,8.4) D10(-3.6,8.4) D11(-2.8,8.4) D12(-2,8.4) D13(-1.2,8.4) D14(-0.4,8.4) D15(0.4,8.4) D16(1.2,8.4) D17(2,8.4) D18(2.8,8.4) D19(3.6,8.4) D20(4.4,8.4) D21(5.2,8.4) D22(6,8.4) D23(6.8,8.4) D24(7.6,8.4) D26(9.2,8.4) D27(10,8.4) D28(10.8,8.4) E1(-10.8,7.6) E2(-10,7.6) E3(-9.2,7.6) E4(-8.4,7.6) E5(-7.6,7.6) E6(-6.8,7.6) E7(-6,7.6) E8(-5.2,7.6) E9(-4.4,7.6) E10(-3.6,7.6) E11(-2.8,7.6) E12(-2,7.6) E13(-1.2,7.6) E14(-0.4,7.6) E15(0.4,7.6) E16(1.2,7.6) E17(2,7.6) E18(2.8,7.6) E19(3.6,7.6) E20(4.4,7.6) E21(5.2,7.6) E22(6,7.6) E23(6.8,7.6) E24(7.6,7.6) E25(8.4,7.6) E26(9.2,7.6) E27(10,7.6) E28(10.8,7.6) F1(-10.8,6.8) F2(-10,6.8) F3(-9.2,6.8) F4(-8.4,6.8) F5(-7.6,6.8) F6(-6.8,6.8) F7(-6,6.8) F8(-5.2,6.8) F9(-4.4,6.8) F10(-3.6,6.8) F11(-2.8,6.8) F12(-2,6.8) F13(-1.2,6.8) F14(-0.4,6.8) F15(0.4,6.8) F16(1.2,6.8) F17(2,6.8) F18(2.8,6.8) F19(3.6,6.8) F20(4.4,6.8) F21(5.2,6.8) F22(6,6.8) F23(6.8,6.8) F24(7.6,6.8) F25(8.4,6.8) F26(9.2,6.8) F27(10,6.8) F28(10.8,6.8) G1(-10.8,6) G2(-10,6) G4(-8.4,6) G5(-7.6,6) G6(-6.8,6) G7(-6,6) G8(-5.2,6) G9(-4.4,6) G10(-3.6,6) G11(-2.8,6) G12(-2,6) G13(-1.2,6) G14(-0.4,6) G15(0.4,6) G16(1.2,6) G17(2,6) G18(2.8,6) G19(3.6,6) G20(4.4,6) G21(5.2,6) G22(6,6) G23(6.8,6) G24(7.6,6) G25(8.4,6) G26(9.2,6) G27(10,6) G28(10.8,6) H1(-10.8,5.2) H2(-10,5.2) H3(-9.2,5.2) H4(-8.4,5.2) H5(-7.6,5.2) H6(-6.8,5.2) H7(-6,5.2) H8(-5.2,5.2) H9(-4.4,5.2) H10(-3.6,5.2) H11(-2.8,5.2) H12(-2,5.2) H13(-1.2,5.2) H14(-0.4,5.2) H15(0.4,5.2) H16(1.2,5.2) H17(2,5.2) H18(2.8,5.2) H19(3.6,5.2) H20(4.4,5.2) H21(5.2,5.2) H22(6,5.2) H23(6.8,5.2) H24(7.6,5.2) H25(8.4,5.2) H26(9.2,5.2) H27(10,5.2) H28(10.8,5.2) J1(-10.8,4.4) J2(-10,4.4) J3(-9.2,4.4) J4(-8.4,4.4) J5(-7.6,4.4) J6(-6.8,4.4) J7(-6,4.4) J8(-5.2,4.4) J9(-4.4,4.4) J10(-3.6,4.4) J11(-2.8,4.4) J12(-2,4.4) J13(-1.2,4.4) J14(-0.4,4.4) J15(0.4,4.4) J16(1.2,4.4) J17(2,4.4) J18(2.8,4.4) J19(3.6,4.4) J20(4.4,4.4) J21(5.2,4.4) J22(6,4.4) J23(6.8,4.4) J24(7.6,4.4) J25(8.4,4.4) J26(9.2,4.4) J27(10,4.4) J28(10.8,4.4) K1(-10.8,3.6) K2(-10,3.6) K4(-8.4,3.6) K5(-7.6,3.6) K6(-6.8,3.6) K7(-6,3.6) K8(-5.2,3.6) K9(-4.4,3.6) K10(-3.6,3.6) K11(-2.8,3.6) K12(-2,3.6) K13(-1.2,3.6) K14(-0.4,3.6) K15(0.4,3.6) K16(1.2,3.6) K17(2,3.6) K18(2.8,3.6) K19(3.6,3.6) K20(4.4,3.6) K21(5.2,3.6) K22(6,3.6) K23(6.8,3.6) K24(7.6,3.6) K25(8.4,3.6) K27(10,3.6) K28(10.8,3.6) L1(-10.8,2.8) L2(-10,2.8) L3(-9.2,2.8) L4(-8.4,2.8) L5(-7.6,2.8) L6(-6.8,2.8) L7(-6,2.8) L8(-5.2,2.8) L9(-4.4,2.8) L10(-3.6,2.8) L11(-2.8,2.8) L12(-2,2.8) L13(-1.2,2.8) L14(-0.4,2.8) L15(0.4,2.8) L16(1.2,2.8) L17(2,2.8) L18(2.8,2.8) L19(3.6,2.8) L20(4.4,2.8) L21(5.2,2.8) L22(6,2.8) L23(6.8,2.8) L24(7.6,2.8) L25(8.4,2.8) L26(9.2,2.8) L27(10,2.8) L28(10.8,2.8) M1(-10.8,2) M2(-10,2) M3(-9.2,2) M4(-8.4,2) M5(-7.6,2) M6(-6.8,2) M7(-6,2) M8(-5.2,2) M9(-4.4,2) M10(-3.6,2) M11(-2.8,2) M12(-2,2) M13(-1.2,2) M14(-0.4,2) M15(0.4,2) M16(1.2,2) M17(2,2) M18(2.8,2) M19(3.6,2) M20(4.4,2) M21(5.2,2) M22(6,2) M23(6.8,2) M24(7.6,2) M25(8.4,2) M26(9.2,2) M27(10,2) M28(10.8,2) N1(-10.8,1.2) N2(-10,1.2) N4(-8.4,1.2) N5(-7.6,1.2) N6(-6.8,1.2) N7(-6,1.2) N8(-5.2,1.2) N9(-4.4,1.2) N10(-3.6,1.2) N11(-2.8,1.2) N12(-2,1.2) N13(-1.2,1.2) N14(-0.4,1.2) N15(0.4,1.2) N16(1.2,1.2) N17(2,1.2) N18(2.8,1.2) N19(3.6,1.2) N20(4.4,1.2) N21(5.2,1.2) N22(6,1.2) N23(6.8,1.2) N24(7.6,1.2) N25(8.4,1.2) N27(10,1.2) N28(10.8,1.2) P1(-10.8,0.4) P2(-10,0.4) P3(-9.2,0.4) P4(-8.4,0.4) P5(-7.6,0.4) P6(-6.8,0.4) P7(-6,0.4) P8(-5.2,0.4) P9(-4.4,0.4) P10(-3.6,0.4) P11(-2.8,0.4) P12(-2,0.4) P13(-1.2,0.4) P14(-0.4,0.4) P15(0.4,0.4) P16(1.2,0.4) P17(2,0.4) P18(2.8,0.4) P19(3.6,0.4) P20(4.4,0.4) P21(5.2,0.4) P22(6,0.4) P23(6.8,0.4) P24(7.6,0.4) P25(8.4,0.4) P26(9.2,0.4) P27(10,0.4) P28(10.8,0.4) R1(-10.8,-0.4) R2(-10,-0.4) R3(-9.2,-0.4) R4(-8.4,-0.4) R5(-7.6,-0.4) R6(-6.8,-0.4) R7(-6,-0.4) R8(-5.2,-0.4) R9(-4.4,-0.4) R10(-3.6,-0.4) R11(-2.8,-0.4) R12(-2,-0.4) R13(-1.2,-0.4) R14(-0.4,-0.4) R15(0.4,-0.4) R16(1.2,-0.4) R17(2,-0.4) R18(2.8,-0.4) R19(3.6,-0.4) R20(4.4,-0.4) R21(5.2,-0.4) R22(6,-0.4) R23(6.8,-0.4) R24(7.6,-0.4) R25(8.4,-0.4) R26(9.2,-0.4) R27(10,-0.4) R28(10.8,-0.4) T1(-10.8,-1.2) T2(-10,-1.2) T4(-8.4,-1.2) T5(-7.6,-1.2) T6(-6.8,-1.2) T7(-6,-1.2) T8(-5.2,-1.2) T9(-4.4,-1.2) T10(-3.6,-1.2) T11(-2.8,-1.2) T12(-2,-1.2) T13(-1.2,-1.2) T14(-0.4,-1.2) T15(0.4,-1.2) T16(1.2,-1.2) T17(2,-1.2) T18(2.8,-1.2) T19(3.6,-1.2) T20(4.4,-1.2) T21(5.2,-1.2) T22(6,-1.2) T23(6.8,-1.2) T24(7.6,-1.2) T25(8.4,-1.2) T27(10,-1.2) T28(10.8,-1.2) U1(-10.8,-2) U2(-10,-2) U3(-9.2,-2) U4(-8.4,-2) U5(-7.6,-2) U6(-6.8,-2) U7(-6,-2) U8(-5.2,-2) U9(-4.4,-2) U10(-3.6,-2) U11(-2.8,-2) U12(-2,-2) U13(-1.2,-2) U14(-0.4,-2) U15(0.4,-2) U16(1.2,-2) U17(2,-2) U18(2.8,-2) U19(3.6,-2) U20(4.4,-2) U21(5.2,-2) U22(6,-2) U23(6.8,-2) U24(7.6,-2) U25(8.4,-2) U26(9.2,-2) U27(10,-2) U28(10.8,-2) V1(-10.8,-2.8) V2(-10,-2.8) V3(-9.2,-2.8) V4(-8.4,-2.8) V5(-7.6,-2.8) V6(-6.8,-2.8) V7(-6,-2.8) V8(-5.2,-2.8) V9(-4.4,-2.8) V10(-3.6,-2.8) V11(-2.8,-2.8) V12(-2,-2.8) V13(-1.2,-2.8) V14(-0.4,-2.8) V15(0.4,-2.8) V16(1.2,-2.8) V17(2,-2.8) V18(2.8,-2.8) V19(3.6,-2.8) V20(4.4,-2.8) V21(5.2,-2.8) V22(6,-2.8) V23(6.8,-2.8) V24(7.6,-2.8) V25(8.4,-2.8) V26(9.2,-2.8) V27(10,-2.8) V28(10.8,-2.8) W1(-10.8,-3.6) W2(-10,-3.6) W4(-8.4,-3.6) W5(-7.6,-3.6) W6(-6.8,-3.6) W7(-6,-3.6) W8(-5.2,-3.6) W9(-4.4,-3.6) W10(-3.6,-3.6) W11(-2.8,-3.6) W12(-2,-3.6) W13(-1.2,-3.6) W14(-0.4,-3.6) W15(0.4,-3.6) W16(1.2,-3.6) W17(2,-3.6) W18(2.8,-3.6) W19(3.6,-3.6) W20(4.4,-3.6) W21(5.2,-3.6) W22(6,-3.6) W23(6.8,-3.6) W24(7.6,-3.6) W25(8.4,-3.6) W27(10,-3.6) W28(10.8,-3.6) Y1(-10.8,-4.4) Y2(-10,-4.4) Y3(-9.2,-4.4) Y4(-8.4,-4.4) Y5(-7.6,-4.4) Y6(-6.8,-4.4) Y7(-6,-4.4) Y8(-5.2,-4.4) Y9(-4.4,-4.4) Y10(-3.6,-4.4) Y11(-2.8,-4.4) Y12(-2,-4.4) Y13(-1.2,-4.4) Y14(-0.4,-4.4) Y15(0.4,-4.4) Y16(1.2,-4.4) Y17(2,-4.4) Y18(2.8,-4.4) Y19(3.6,-4.4) Y20(4.4,-4.4) Y21(5.2,-4.4) Y22(6,-4.4) Y23(6.8,-4.4) Y24(7.6,-4.4) Y25(8.4,-4.4) Y26(9.2,-4.4) Y27(10,-4.4) Y28(10.8,-4.4)
